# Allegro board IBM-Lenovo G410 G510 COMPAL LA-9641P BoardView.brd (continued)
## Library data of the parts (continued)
Q107 Q108 Q110 Q111 Q113 Q116 Q118 Q120 QV1 QV2 QV6 QV7 QV9 = 2N7002_SOT23-3
Q121 QV8 = AP2301GN-HF_SOT23-3
R297 R299 R300 R302 R550-R553 R813 RT1 = R0805_0OHM
RL14 = R_0805
RP1 RP2 RP5 RP6 RP9 RP10 RP12 RP16-RP19 RP21-RP23 = RP_0804_8P4R
RP13-RP15 = RP_1206_10P8R
SW4-SW7 = SW_TJG-533-V-T-R_6P
T1-T4 T6 T12-T28 T31 T66 TV12-TV15 = TPC12
TL1 = BOTH_NS0013LF_16P
U1 = 74AHC1G09GW_TSSOP5
U4 = DH82LPMS-QC4C_FCBGA_695P_A39
U6 UV2 = NC7SZ08P5X_NL_SC70-5
U8 = MX25L1605AM2C-12G_SO8
U9 = ADM1032ARMZ-2REEL_MSOP8
U10 = TPD7S019-15DBQR_SSOP16
U31 = KB9012QF-A2_LQFP128_14X14
U35 U36 = G547I2P81U_MSOP8
U38 U39 = DMN3030LSS-13_SOP8L-8
U72 = APL3512ABI-TRG_SOT23-5
U73 = AP2330W-7_SC59-3
UA1 = CX20751-11Z_QFN40_5X5
UL1 = AR8161-AL3A-R_QFN40_5X5
UT2 = RTD2132S-GR_QFN32_5X5
UV1 = MARS-PRO_FCBGA_962P_A39
UV4 = AO4304L_SO8
UV5-UV8 = MT41J128M16JT-093_FBGA_96P_A39
UV9-UV12 = K4W4G1646B-HC11_FBGA_96P_A39
Y1 = Y_CM31532768DZFT_2P
Y2 YL1 YV1 = Y_X3G025000DC1H_4P

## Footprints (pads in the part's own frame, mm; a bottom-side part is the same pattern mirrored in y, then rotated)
1N4148WS-7-F_SOD323-2
  rect 1.346x0.66 smd: 1(0,0) 2(2.4,0)
1SS355_SOD323-2
  rect 0.787x0.889 smd: 1(0,0) 2(2.2,0)
2N7002_SOT23-3
  oval 1.016x1.524 smd: 1(0,0) 2(0.965,2.083) 3(-0.965,2.083)
2N7002DW-7-F_SOT363-6
  oval 0.432x0.61 smd: 1(0,0) 2(0.65,0) 3(1.3,0) 4(1.3,1.9) 5(0.65,1.9) 6(0,1.9)
2N7002DW-T-R7_SOT363-6
  oval 0.381x1.397 smd: 1(0,0) 2(0.65,0) 3(1.3,0) 4(1.3,1.725) 5(0.65,1.725) 6(0,1.725)
2N7002H_SOT23-3
  oval 1.016x1.524 smd: 1(0,0) 2(0.965,2.083) 3(-0.965,2.083)
2N7002KW_SOT323-3
  oval 0.813x0.914 smd: 1(0,0) 2(0.65,1.6) 3(-0.65,1.6)
2N7002W-T-R7_SOT323-3
  oval 0.813x0.914 smd: 1(0,0) 2(0.65,1.6) 3(-0.65,1.6)
74AHC1G09GW_TSSOP5
  oval 0.381x1.346 smd: 1(0,0) 2(0.65,0) 3(1.3,0) 4(1.3,1.79) 5(0,1.79)
ACES_50208-00601-P01_6P
  oval 0.508x0.991 smd: 1(0,0) 2(-0.8,0) 3(-1.6,0) 4(-2.4,0) 5(-3.2,0) 6(-4,0)
  rect 1.194x1.702 smd: 7(-5.3,-1.95) 8(1.3,-1.95)
ACES_50271-0020N-001_2P
  oval 0.787x1.6 smd: 1(0,0) 2(1.25,0)
  rect 2.108x2.997 smd: 3(3.8,-2.9) 4(-2.55,-2.9)
ACES_50312-00541-001_5P-T
  round 1.397 hole 0.991: 1(0,0) 2(2,0) 3(4,0) 4(6,0) 5(8,0)
ACES_85205-0400_4P
  oval 0.813x1.626 smd: 1(0,0) 2(1.25,0) 3(2.5,0) 4(3.75,0)
  rect 2.032x3.048 smd: 5(-2.55,-2.9) 6(6.3,-2.9)
ACES_85205-04001_4P
  oval 0.787x1.6 smd: 1(0,0) 2(1.25,0) 3(2.5,0) 4(3.75,0)
  rect 2.108x2.997 smd: 5(-2.55,-2.9) 6(6.3,-2.9)
ACES_88058-060N_6P
  oval 0.61x1.092 smd: 1(0,0) 2(-1,0) 3(-2,0) 4(-3,0) 5(-4,0) 6(-5,0)
  rect 2.388x2.997 smd: 7(2.9,-2.05) 8(-7.9,-2.05)
ACES_88341-3001_30P
  round 1.092 hole 1.092 unplated: (-2.3,-1.95) (16.8,-1.95)
  oval 0.254x1.295 smd: 1(0,0) 2(0.5,0) 3(1,0) 4(1.5,0) 5(2,0) 6(2.5,0) 7(3,0) 8(3.5,0) 9(4,0) 10(4.5,0) 11(5,0) 12(5.5,0) 13(6,0) 14(6.5,0) 15(7,0) 16(7.5,0) 17(8,0) 18(8.5,0) 19(9,0) 20(9.5,0) 21(10,0) 22(10.5,0) 23(11,0) 24(11.5,0) 25(12,0) 26(12.5,0) 27(13,0) 28(13.5,0) 29(14,0) 30(14.5,0)
  rect 1.549x3.404 smd: 31(-4.125,-5.85) 32(18.625,-5.85)
  rect 2.007x2.997 smd: 33(3.5,-6.05) 34(11,-6.05)
ACES_88514-2401_24P-T
  oval 0.61x1.295 smd: 1(0,0) 2(-1,0) 3(-2,0) 4(-3,0) 5(-4,0) 6(-5,0) 7(-6,0) 8(-7,0) 9(-8,0) 10(-9,0) 11(-10,0) 12(-11,0) 13(-12,0) 14(-13,0) 15(-14,0) 16(-15,0) 17(-16,0) 18(-17,0) 19(-18,0) 20(-19,0) 21(-20,0) 22(-21,0) 23(-22,0) 24(-23,0)
  rect 2.159x2.21 smd: 25(-25.825,-3.05) 26(2.825,-3.05)
ACES_88514-3001_30P
  oval 0.61x1.295 smd: 1(0,0) 2(1,0) 3(2,0) 4(3,0) 5(4,0) 6(5,0) 7(6,0) 8(7,0) 9(8,0) 10(9,0) 11(10,0) 12(11,0) 13(12,0) 14(13,0) 15(14,0) 16(15,0) 17(16,0) 18(17,0) 19(18,0) 20(19,0) 21(20,0) 22(21,0) 23(22,0) 24(23,0) 25(24,0) 26(25,0) 27(26,0) 28(27,0) 29(28,0) 30(29,0)
  rect 2.159x2.21 smd: 31(-2.825,-3.05) 32(31.825,-3.05)
ADM1032ARMZ-2REEL_MSOP8
  oval 0.381x1.626 smd: 1(0,0) 2(0.65,0) 3(1.3,0) 4(1.95,0) 5(1.95,4.3) 6(1.3,4.3) 7(0.65,4.3) 8(0,4.3)
ALLTO_C18518-11305-L_13P-T
  round 1.194 hole 1.194 unplated: (-19.18,-1.56) (0.42,-1.56)
  round 1.067 hole 0.711: 1(0,0) 2(-1.27,0) 3(-2.54,0) 4(-3.81,0) 5(-5.08,0) 6(-6.35,0) 7(-7.62,0)
  round 1.016 hole 0.61: 8(-13.83,1) 9(-14.83,0) 10(-15.83,1) 11(-16.83,0) 12(-17.83,1) 13(-18.83,0)
  oval 1.803x3.302 hole 0.991x2.489: 14(-20.98,-0.29) 15(2.22,-0.29)
AO4304L_SO8
  oval 0.635x1.854 smd: 1(0,0) 2(1.27,0) 3(2.54,0) 4(3.81,0) 5(3.81,5.165) 6(2.54,5.165) 7(1.27,5.165) 8(0,5.165)
AO4407A_SO8
  oval 0.635x1.854 smd: 1(0,0) 2(1.27,0) 3(2.54,0) 4(3.81,0) 5(3.81,5.165) 6(2.54,5.165) 7(1.27,5.165) 8(0,5.165)
AO4466L_SO8
  oval 0.635x1.854 smd: 1(0,0) 2(1.27,0) 3(2.54,0) 4(3.81,0) 5(3.81,5.165) 6(2.54,5.165) 7(1.27,5.165) 8(0,5.165)
AP2301GN-HF_SOT23-3
  oval 1.016x1.524 smd: 1(0,0) 2(0.965,2.083) 3(-0.965,2.083)
AP2330W-7_SC59-3
  oval 0.787x0.991 smd: 1(0,0) 2(-0.95,-2.4) 3(0.95,-2.4)
APL3512ABI-TRG_SOT23-5
  oval 0.61x1.041 smd: 1(0,0) 2(0.95,0) 3(1.9,0) 4(1.9,2.7) 5(0,2.7)
AR8161-AL3A-R_QFN40_5X5
  oval 0.203x1.016 smd: 1(0,0) 2(0.4,0) 3(0.8,0) 4(1.2,0) 5(1.6,0) 6(2,0) 7(2.4,0) 8(2.8,0) 9(3.2,0) 10(3.6,0) 21(3.6,4.975) 22(3.2,4.975) 23(2.8,4.975) 24(2.4,4.975) 25(2,4.975) 26(1.6,4.975) 27(1.2,4.975) 28(0.8,4.975) 29(0.4,4.975) 30(0,4.975)
  oval 1.016x0.203 smd: 11(4.288,0.688) 12(4.288,1.088) 13(4.288,1.488) 14(4.288,1.888) 15(4.288,2.288) 16(4.288,2.688) 17(4.288,3.088) 18(4.288,3.488) 19(4.288,3.888) 20(4.288,4.288) 31(-0.688,4.288) 32(-0.688,3.888) 33(-0.688,3.488) 34(-0.688,3.088) 35(-0.688,2.688) 36(-0.688,2.288) 37(-0.688,1.888) 38(-0.688,1.488) 39(-0.688,1.088) 40(-0.688,0.688)
  rect 3.302x3.302 smd: 41(1.8,2.488)
AZ5125-02SPR7G_SOT23-3
  oval 1.016x1.524 smd: 1(0,0) 2(0.965,2.083) 3(-0.965,2.083)
AZC099-04SPR7G_SOT23-6
  oval 0.559x1.092 smd: 1(0,0) 2(0.95,0) 3(1.9,0) 4(1.9,2.5) 5(0.95,2.5) 6(0,2.5)
BELLW_80003-8041_52P
  round 1.6 hole 1.6 unplated: (-0.7,4.1)
  round 1.092 hole 1.092 unplated: (24.3,4.1)
  oval 0.61x2.007 smd: 1(0,0) 2(0.4,8.2) 3(0.8,0) 4(1.2,8.2) 5(1.6,0) 6(2,8.2) 7(2.4,0) 8(2.8,8.2) 9(3.2,0) 10(3.6,8.2) 11(4,0) 12(4.4,8.2) 13(4.8,0) 14(5.2,8.2) 15(5.6,0) 16(6,8.2) 17(9.6,0) 18(10,8.2) 19(10.4,0) 20(10.8,8.2) 21(11.2,0) 22(11.6,8.2) 23(12,0) 24(12.4,8.2) 25(12.8,0) 26(13.2,8.2) 27(13.6,0) 28(14,8.2) 29(14.4,0) 30(14.8,8.2) 31(15.2,0) 32(15.6,8.2) 33(16,0) 34(16.4,8.2) 35(16.8,0) 36(17.2,8.2) 37(17.6,0) 38(18,8.2) 39(18.4,0) 40(18.8,8.2) 41(19.2,0) 42(19.6,8.2) 43(20,0) 44(20.4,8.2) 45(20.8,0) 46(21.2,8.2) 47(21.6,0) 48(22,8.2) 49(22.4,0) 50(22.8,8.2) 51(23.2,0) 52(23.6,8.2)
  rect 2.311x3.2 smd: 53(-2.85,0.6) 54(26.45,0.6)
BOTH_NS0013LF_16P
  oval 0.762x1.905 smd: 1(0,0) 2(1.27,0) 3(2.54,0) 4(3.81,0) 5(5.08,0) 6(6.35,0) 7(7.62,0) 8(8.89,0) 9(8.89,8.8) 10(7.62,8.8) 11(6.35,8.8) 12(5.08,8.8) 13(3.81,8.8) 14(2.54,8.8) 15(1.27,8.8) 16(0,8.8)
BQ24737RGRR_VQFN20_3P5X3P5
  oval 0.254x1.041 smd: 1(0,0) 2(0.5,0) 3(1,0) 4(1.5,0) 5(2,0) 11(2,3.45) 12(1.5,3.45) 13(1,3.45) 14(0.5,3.45) 15(0,3.45)
  oval 1.041x0.254 smd: 6(2.725,0.725) 7(2.725,1.225) 8(2.725,1.725) 9(2.725,2.225) 10(2.725,2.725) 16(-0.725,2.725) 17(-0.725,2.225) 18(-0.725,1.725) 19(-0.725,1.225) 20(-0.725,0.725)
  rect 2.057x2.057 smd: 21(1,1.725)
BS4200N-C-LV_SMB-F2
  rect 2.159x2.743 smd: 1(0,0) 2(4.42,0)
C_6SVPE220MX
  oval 3.505x1.6 smd: 1(0,0) 2(5.6,0)
C_0402
  rect 0.508x0.559 smd: 1(0,0) 2(0.914,0)
C_0603
  rect 0.635x0.889 smd: 1(0,0) 2(1.397,0)
C_0805
  rect 0.813x1.397 smd: 1(0,0) 2(1.702,0)
C_B2
  rect 1.346x2.692 smd: 1(0,0) 2(-2.75,0)
C_D2
  rect 2.388x2.794 smd: 1(0,0) 2(6.4,0)
C_EEEFZ1E101P
  oval 3.2x1.6 smd: 1(0,0) 2(5,0)
C_FP-2R5ME331M-SLR
  oval 3.505x1.6 smd: 1(0,0) 2(-5.6,0)
C_MP2VLPS330MC4R2
  oval 3.505x1.6 smd: 1(0,0) 2(-5.6,0)
C_MP6VL220MC6
  oval 3.505x1.6 smd: 1(0,0) 2(5.6,0)
C_MP6VLPS220MC4R2
  oval 3.505x1.6 smd: 1(0,0) 2(-5.6,0)
C_MVY25VC220MH10E0-J
  oval 4.191x2.21 smd: 1(0,0) 2(-7.3,0)
CH751H-40PT_SOD323-2
  rect 0.711x0.711 smd: 1(0,0) 2(2.33,0)
CHENG_MBK1608121YZF_2P
  rect 0.991x0.787 smd: 1(0,0) 2(1.6,0)
CHENG_SMB3025500YA_2P
  rect 2.997x1.803 smd: 1(0,0) 2(4,0)
CONTE_80431-5K1-152_15P
  oval 0.965x1.321 hole 0.711: 1(0,0) 2(2.29,0) 3(4.58,0) 4(6.87,0) 5(9.16,0) 6(-1.145,0) 7(1.145,0) 8(3.435,0) 9(5.725,0) 10(8.015,0)
  round 1.016 hole 0.711: 11(0,1.4) 12(2.29,1.4) 13(4.58,1.4) 14(6.87,1.4) 15(9.16,1.4)
  oval 1.372x3.251 hole 0.61x2.489: 16(-5.47,-0.1) 17(14.63,-0.1)
CSD87351Q5D_SON8-7
  oval 1.93x0.838 smd: 1(0,0)
  oval 0.66x0.838 smd: 2(1.905,0) 3(3.175,0) 4(3.175,5.39) 5(1.905,5.39) 6(0.635,5.39) 7(-0.635,5.39)
  custom 0.87x0.87 smd: 8(1.27,2.695)
CVILU_CF06041H0RB-NH_4P
  oval 0.305x1.143 smd: 1(0,0) 2(1,0) 3(2,0) 4(3,0)
  rect 1.397x2.311 smd: 5(-1.75,-3.825) 6(4.75,-3.825)
CX20751-11Z_QFN40_5X5
  oval 0.203x1.016 smd: 1(0,0) 2(0.4,0) 3(0.8,0) 4(1.2,0) 5(1.6,0) 6(2,0) 7(2.4,0) 8(2.8,0) 9(3.2,0) 10(3.6,0) 21(3.6,4.975) 22(3.2,4.975) 23(2.8,4.975) 24(2.4,4.975) 25(2,4.975) 26(1.6,4.975) 27(1.2,4.975) 28(0.8,4.975) 29(0.4,4.975) 30(0,4.975)
  oval 1.016x0.203 smd: 11(4.288,0.688) 12(4.288,1.088) 13(4.288,1.488) 14(4.288,1.888) 15(4.288,2.288) 16(4.288,2.688) 17(4.288,3.088) 18(4.288,3.488) 19(4.288,3.888) 20(4.288,4.288) 31(-0.688,4.288) 32(-0.688,3.888) 33(-0.688,3.488) 34(-0.688,3.088) 35(-0.688,2.688) 36(-0.688,2.288) 37(-0.688,1.888) 38(-0.688,1.488) 39(-0.688,1.088) 40(-0.688,0.688)
  rect 3.302x3.302 smd: 41(1.8,2.488)
CYNTE_PCMB063T-1R0MS_2P
  rect 2.159x3.505 smd: 1(0,0) 2(5.85,0)
CYNTE_PCMB063T-100MS_2P
  rect 2.362x3.505 smd: 1(0,0) 2(6.05,0)
CYNTE_PCMB104T-1R0MH_2P
  rect 3.81x3.988 smd: 1(0,0) 2(9.2,0)
CYNTE_PDME064T-R36MS1R405_4P
  custom 0.686x0.686 smd: 1(0,0) 4(8.509,0)
  rect 2.362x0.508 smd: 2(1.448,0) 3(7.061,0)
CYNTE_PG031B-4R7MS_2P
  rect 0.889x1.194 smd: 1(0,0) 2(2.2,0)
CYNTE_PHT32251B-1R0MS_2P
  rect 0.991x2.591 smd: 1(0,0) 2(2.3,0)
DAN202UT106_SC70-3
  oval 0.787x0.889 smd: 1(0,0) 2(0.65,1.6) 3(-0.65,1.6)
DELTA_SIA4012-4R7M_2P
  rect 1.194x4.191 smd: 1(0,0) 2(3,0)
DH82LPMS-QC4C_FCBGA_695P_A39
  round 0.483 smd: A2(0.624,0) A44(18.101,0) B1(0,-0.624) B45(18.625,-0.524) BD1(0,-18.101) BD45(18.625,-18.101) BE2(0.524,-18.625) BE44(18.101,-18.625)
  round 0.356 smd: A4(1.217,0) A5(1.81,0) A41(16.915,0) A43(17.508,0) B2(0.603,-0.603) B44(18.022,-0.603) BA1(0,-16.915) BA45(18.625,-16.915) BC1(0,-17.508) BC45(18.625,-17.508) BD2(0.603,-18.022) BD44(18.022,-18.022) BE3(1.117,-18.625) BE5(1.71,-18.625) BE41(16.915,-18.625) BE43(17.508,-18.625) C45(18.625,-1.117) D1(0,-1.217) E1(0,-1.81) E45(18.625,-1.71)
  round 0.33 smd: A6(2.483,0) A40(16.242,0) AY1(0,-16.242) AY45(18.625,-16.242) BE6(2.383,-18.625) BE40(16.242,-18.625) F1(0,-2.483) F45(18.625,-2.383)
  round 0.305 smd: A8(3.216,0) A10(4.029,0) A12(4.842,0) A14(5.655,0) A16(6.468,0) A18(7.28,0) A20(8.093,0) A22(8.906,0) A24(9.719,0) A26(10.532,0) A28(11.344,0) A30(12.157,0) A32(12.97,0) A34(13.783,0) A36(14.596,0) A38(15.408,0) AA2(0.452,-8.478) AA4(1.336,-8.5) AA14(5.515,-8.827) AA16(6.328,-8.827) AA18(7.141,-8.827) AA20(7.954,-8.827) AA22(8.766,-8.827) AA24(9.579,-8.827) AA26(10.392,-8.827) AA28(11.205,-8.827) AA30(12.018,-8.827) AA32(12.83,-8.827) AA42(17.289,-8.5) AA44(18.173,-8.521) AB1(0,-8.906) AB3(0.904,-8.906) AB6(1.934,-9.008) AB7(2.531,-9.008) AB8(3.128,-9.008) AB10(3.724,-9.008) AB11(4.321,-9.008) AB12(4.918,-9.008) AB34(13.707,-9.008) AB35(14.304,-9.008) AB36(14.9,-9.008) AB38(15.497,-9.008) AB39(16.094,-9.008) AB40(16.691,-9.008) AB43(17.721,-8.906) AB45(18.625,-8.906) AC2(0.472,-9.312) AC44(18.152,-9.312) AD1(0,-9.719) AD3(0.904,-9.719) AD6(1.934,-9.617) AD7(2.531,-9.617) AD8(3.128,-9.617) AD10(3.724,-9.617) AD11(4.321,-9.617) AD12(4.918,-9.617) AD14(5.515,-9.488) AD16(6.328,-9.488) AD18(7.141,-9.488) AD20(7.954,-9.488) AD22(8.766,-9.488) AD24(9.579,-9.488) AD26(10.392,-9.488) AD28(11.205,-9.488) AD30(12.018,-9.488) AD32(12.83,-9.488) AD34(13.707,-9.617) AD35(14.304,-9.617) AD36(14.9,-9.617) AD38(15.497,-9.617) AD39(16.094,-9.617) AD40(16.691,-9.617) AD43(17.721,-9.719) AD45(18.625,-9.719) AE2(0.452,-10.103) AE4(1.336,-10.125) AE14(5.515,-10.148) AE16(6.328,-10.148) AE18(7.141,-10.148) AE20(7.954,-10.148) AE22(8.766,-10.148) AE24(9.579,-10.148) AE26(10.392,-10.148) AE28(11.205,-10.148) AE30(12.018,-10.148) AE32(12.83,-10.148) AE42(17.289,-10.125) AE44(18.173,-10.147) AF1(0,-10.532) AF3(0.904,-10.532) AF6(1.934,-10.595) AF7(2.531,-10.595) AF8(3.128,-10.595) AF10(3.724,-10.595) AF11(4.321,-10.595) AF12(4.918,-10.595) AF34(13.707,-10.595) AF35(14.304,-10.595) AF36(14.9,-10.595) AF38(15.497,-10.595) AF39(16.094,-10.595) AF40(16.691,-10.595) AF43(17.721,-10.532) AF45(18.625,-10.532) AG2(0.472,-10.938) AG14(5.515,-10.808) AG16(6.328,-10.808) AG18(7.141,-10.808) AG20(7.954,-10.808) AG22(8.766,-10.808) AG24(9.579,-10.808) AG26(10.392,-10.808) AG28(11.205,-10.808) AG30(12.018,-10.808) AG32(12.83,-10.808) AG44(18.152,-10.938) AH1(0,-11.344) AH3(0.904,-11.344) AH43(17.721,-11.344) AH45(18.625,-11.344) AJ2(0.452,-11.729) AJ4(1.336,-11.751) AJ6(1.934,-11.573) AJ7(2.531,-11.573) AJ8(3.128,-11.573) AJ10(3.724,-11.573) AJ11(4.321,-11.573) AJ12(4.918,-11.573) AJ14(5.515,-11.469) AJ16(6.328,-11.469) AJ18(7.141,-11.469) AJ20(7.954,-11.469) AJ22(8.766,-11.469) AJ24(9.579,-11.469) AJ26(10.392,-11.469) AJ28(11.205,-11.469) AJ30(12.018,-11.469) AJ32(12.83,-11.469) AJ34(13.707,-11.573) AJ35(14.304,-11.573) AJ36(14.9,-11.573) AJ38(15.497,-11.573) AJ39(16.094,-11.573) AJ40(16.691,-11.573) AJ42(17.289,-11.751) AJ44(18.173,-11.773) AK1(0,-12.157) AK3(0.904,-12.157) AK14(5.515,-12.129) AK16(6.328,-12.129) AK18(7.141,-12.129) AK20(7.954,-12.129) AK22(8.766,-12.129) AK24(9.579,-12.129) AK26(10.392,-12.129) AK28(11.205,-12.129) AK30(12.018,-12.129) AK32(12.83,-12.129) AK43(17.721,-12.157) AK45(18.625,-12.157) AL2(0.472,-12.564) AL6(1.934,-12.551) AL7(2.531,-12.551) AL8(3.128,-12.551) AL10(3.724,-12.551) AL11(4.321,-12.551) AL12(4.918,-12.551) AL34(13.707,-12.551) AL35(14.304,-12.551) AL36(14.9,-12.551) AL38(15.497,-12.551) AL39(16.094,-12.551) AL40(16.691,-12.551) AL44(18.152,-12.564) AM1(0,-12.97) AM3(0.904,-12.97) AM14(5.515,-12.79) AM16(6.328,-12.79) AM18(7.141,-12.79) AM20(7.954,-12.79) AM22(8.766,-12.79) AM24(9.579,-12.79) AM26(10.392,-12.79) AM28(11.205,-12.79) AM30(12.018,-12.79) AM32(12.83,-12.79) AM43(17.721,-12.97) AM45(18.625,-12.97) AN2(0.452,-13.355) AN4(1.336,-13.376) AN6(1.934,-13.529) AN7(2.531,-13.529) AN8(3.128,-13.529) AN10(3.724,-13.529) AN11(4.321,-13.529) AN34(13.656,-13.529) AN35(14.304,-13.529) AN36(14.9,-13.529) AN38(15.497,-13.529) AN39(16.094,-13.529) AN40(16.691,-13.529) AN42(17.289,-13.376) AN44(18.173,-13.398) AP1(0,-13.783) AP3(0.904,-13.783) AP13(5.096,-13.656) AP15(6.074,-13.707) AP17(7.052,-13.707) AP20(8.03,-13.707) AP22(9.008,-13.707) AP24(9.617,-13.707) AP26(10.595,-13.707) AP29(11.573,-13.707) AP31(12.551,-13.707) AP43(17.721,-13.783) AP45(18.625,-13.783) AR2(0.472,-14.189) AR13(5.096,-14.304) AR15(6.074,-14.304) AR17(7.052,-14.304) AR20(8.03,-14.304) AR22(9.008,-14.304) AR24(9.617,-14.304) AR26(10.595,-14.304) AR29(11.573,-14.304) AR31(12.551,-14.304) AR33(13.529,-14.304) AR44(18.152,-14.189) AT1(0,-14.596) AT3(0.904,-14.596) AT6(1.934,-14.507) AT7(2.531,-14.507) AT8(3.128,-14.507) AT10(4.118,-14.9) AT13(5.096,-14.9) AT15(6.074,-14.9) AT17(7.052,-14.9) AT20(8.03,-14.9) AT22(9.008,-14.9) AT24(9.617,-14.9) AT26(10.595,-14.9) AT29(11.573,-14.9) AT31(12.551,-14.9) AT33(13.529,-14.9) AT36(14.9,-14.507) AT38(15.497,-14.507) AT39(16.094,-14.507) AT40(16.691,-14.507) AT43(17.721,-14.596) AT45(18.625,-14.596) AU2(0.452,-14.98) AU4(1.336,-15.002) AU42(17.289,-15.002) AU44(18.173,-15.024) AV1(0,-15.408) AV3(0.904,-15.408) AV6(1.934,-15.485) AV7(2.531,-15.485) AV10(4.118,-15.497) AV13(5.096,-15.497) AV15(6.074,-15.497) AV17(7.052,-15.497) AV20(8.03,-15.497) AV22(9.008,-15.497) AV24(9.617,-15.497) AV26(10.595,-15.497) AV29(11.573,-15.497) AV31(12.551,-15.497) AV33(13.529,-15.497) AV36(14.507,-15.497) AV40(16.691,-15.485) AV43(17.721,-15.408) AV45(18.625,-15.408) AW2(0.472,-15.815) AW8(3.14,-16.094) AW10(4.118,-16.094) AW13(5.096,-16.094) AW15(6.074,-16.094) AW17(7.052,-16.094) AW20(8.03,-16.094) AW22(9.008,-16.094) AW24(9.617,-16.094) AW26(10.595,-16.094) AW29(11.573,-16.094) AW31(12.551,-16.094) AW33(13.529,-16.094) AW36(14.507,-16.094) AW38(15.485,-16.094) AW40(17.123,-16.221) AW44(18.152,-15.815) AY3(0.978,-16.221) AY5(1.743,-16.051) AY7(2.404,-17.123) AY8(3.14,-16.691) AY10(4.118,-16.691) AY13(5.096,-16.691) AY15(6.074,-16.691) AY17(7.052,-16.691) AY20(8.03,-16.691) AY22(9.008,-16.691) AY24(9.617,-16.691) AY26(10.595,-16.691) AY29(11.573,-16.691) AY31(12.551,-16.691) AY33(13.529,-16.691) AY36(14.507,-16.691) AY38(15.485,-16.691) AY43(17.721,-16.221) B7(2.739,-0.552) B9(3.645,-0.452) B11(4.436,-0.472) B13(5.27,-0.452) B15(6.061,-0.472) B17(6.896,-0.452) B19(7.687,-0.472) B21(8.521,-0.452) B23(9.312,-0.472) B25(10.147,-0.452) B27(10.938,-0.472) B29(11.773,-0.452) B31(12.564,-0.472) B33(13.398,-0.452) B35(14.189,-0.472) B37(15.024,-0.452) B39(15.815,-0.472) BA40(16.051,-16.882) BB9(3.623,-17.289) BB13(5.248,-17.289) BB17(6.874,-17.289) BB21(8.5,-17.289) BB25(10.125,-17.289) BB29(11.751,-17.289) BB33(13.376,-17.289) BB37(15.002,-17.289) BC6(2.404,-17.721) BC8(3.216,-17.721) BC10(4.029,-17.721) BC12(4.842,-17.721) BC14(5.655,-17.721) BC16(6.468,-17.721) BC18(7.28,-17.721) BC20(8.093,-17.721) BC22(8.906,-17.721) BC24(9.719,-17.721) BC26(10.532,-17.721) BC28(11.344,-17.721) BC30(12.157,-17.721) BC32(12.97,-17.721) BC34(13.783,-17.721) BC36(14.596,-17.721) BC38(15.408,-17.721) BC40(16.221,-17.647) BD7(2.81,-18.152) BD9(3.601,-18.173) BD11(4.436,-18.152) BD13(5.227,-18.173) BD15(6.061,-18.152) BD17(6.852,-18.173) BD19(7.687,-18.152) BD21(8.478,-18.173) BD23(9.312,-18.152) BD25(10.103,-18.173) BD27(10.938,-18.152) BD29(11.729,-18.173) BD31(12.564,-18.152) BD33(13.355,-18.173) BD35(14.189,-18.152) BD37(14.98,-18.173) BD39(15.815,-18.152) BE8(3.216,-18.625) BE10(4.029,-18.625) BE12(4.842,-18.625) BE14(5.655,-18.625) BE16(6.468,-18.625) BE18(7.28,-18.625) BE20(8.093,-18.625) BE22(8.906,-18.625) BE24(9.719,-18.625) BE26(10.532,-18.625) BE28(11.344,-18.625) BE30(12.157,-18.625) BE32(12.97,-18.625) BE34(13.783,-18.625) BE36(14.596,-18.625) BE38(15.408,-18.625) C6(2.37,-1.017) C8(3.216,-0.904) C10(4.029,-0.904) C12(4.842,-0.904) C14(5.655,-0.904) C16(6.468,-0.904) C18(7.28,-0.904) C20(8.093,-0.904) C22(8.906,-0.904) C24(9.719,-0.904) C26(10.532,-0.904) C28(11.344,-0.904) C30(12.157,-0.904) C32(12.97,-0.904) C34(13.783,-0.904) C36(14.596,-0.904) C38(15.408,-0.904) C40(16.221,-0.904) D9(3.623,-1.336) D13(5.248,-1.336) D17(6.874,-1.336) D21(8.5,-1.336) D25(10.125,-1.336) D29(11.751,-1.336) D33(13.376,-1.336) D37(15.002,-1.336) E6(2.574,-1.743) F3(0.978,-2.359) F8(3.14,-1.934) F10(4.118,-1.934) F13(5.096,-1.934) F15(6.074,-1.934) F17(7.052,-1.934) F20(8.03,-1.934) F22(9.008,-1.934) F24(9.617,-1.934) F26(10.595,-1.934) F29(11.573,-1.934) F31(12.551,-1.934) F33(13.529,-1.934) F36(14.507,-1.934) F38(15.485,-1.934) F39(16.221,-1.502) F41(16.882,-2.574) F43(17.647,-2.404) G2(0.532,-2.752) G5(1.562,-2.48) G8(3.14,-2.531) G10(4.118,-2.531) G13(5.096,-2.531) G15(6.074,-2.531) G17(7.052,-2.531) G20(8.03,-2.531) G22(9.008,-2.531) G24(9.617,-2.531) G26(10.595,-2.531) G29(11.573,-2.531) G31(12.551,-2.531) G33(13.529,-2.531) G36(14.507,-2.531) G38(15.485,-2.531) G44(18.152,-2.81) H1(0,-3.216) H3(0.904,-3.216) H6(1.934,-3.14) H7(2.531,-3.14) H10(4.118,-3.128) H13(5.096,-3.128) H15(6.074,-3.128) H17(7.052,-3.128) H20(8.03,-3.128) H22(9.008,-3.128) H24(9.617,-3.128) H26(10.595,-3.128) H29(11.573,-3.128) H31(12.551,-3.128) H33(13.529,-3.128) H36(14.507,-3.128) H39(16.094,-3.14) H40(16.691,-3.14) H43(17.721,-3.216) H45(18.625,-3.216) J2(0.452,-3.601) J4(1.336,-3.623) J42(17.289,-3.623) J44(18.173,-3.645) K1(0,-4.029) K3(0.904,-4.029) K6(1.934,-4.118) K7(2.531,-4.118) K8(3.128,-4.118) K10(3.724,-4.118) K13(5.096,-3.724) K15(6.074,-3.724) K17(7.052,-3.724) K20(8.03,-3.724) K22(9.008,-3.724) K24(9.617,-3.724) K26(10.595,-3.724) K29(11.573,-3.724) K31(12.551,-3.724) K33(13.529,-3.724) K36(14.507,-3.724) K38(15.497,-4.118) K39(16.094,-4.118) K40(16.691,-4.118) K43(17.721,-4.029) K45(18.625,-4.029) L2(0.472,-4.436) L13(5.096,-4.321) L15(6.074,-4.321) L17(7.052,-4.321) L20(8.03,-4.321) L22(9.008,-4.321) L24(9.617,-4.321) L26(10.595,-4.321) L29(11.573,-4.321) L31(12.551,-4.321) L33(13.529,-4.321) L44(18.152,-4.436) M1(0,-4.842) M3(0.904,-4.842) M15(6.074,-4.918) M17(7.052,-4.918) M20(8.03,-4.918) M22(9.008,-4.918) M24(9.617,-4.918) M26(10.595,-4.918) M29(11.573,-4.918) M31(12.551,-4.918) M33(13.529,-4.969) M43(17.721,-4.842) M45(18.625,-4.842) N2(0.452,-5.227) N4(1.336,-5.248) N6(1.934,-5.096) N7(2.531,-5.096) N8(3.128,-5.096) N10(3.724,-5.096) N11(4.321,-5.096) N12(4.969,-5.096) N35(14.304,-5.096) N36(14.9,-5.096) N38(15.497,-5.096) N39(16.094,-5.096) N40(16.691,-5.096) N42(17.289,-5.248) N44(18.173,-5.27) P1(0,-5.655) P3(0.904,-5.655) P14(5.515,-5.525) P16(6.328,-5.525) P18(7.141,-5.525) P20(7.954,-5.525) P22(8.766,-5.525) P24(9.579,-5.525) P26(10.392,-5.525) P28(11.205,-5.525) P30(12.018,-5.525) P32(12.83,-5.525) P43(17.721,-5.655) P45(18.625,-5.655) R2(0.472,-6.061) R6(1.934,-6.074) R7(2.531,-6.074) R8(3.128,-6.074) R10(3.724,-6.074) R11(4.321,-6.074) R12(4.918,-6.074) R14(5.515,-6.186) R16(6.328,-6.186) R18(7.141,-6.186) R20(7.954,-6.186) R22(8.766,-6.186) R24(9.579,-6.186) R26(10.392,-6.186) R28(11.205,-6.186) R30(12.018,-6.186) R32(12.83,-6.186) R34(13.707,-6.074) R35(14.304,-6.074) R36(14.9,-6.074) R38(15.497,-6.074) R39(16.094,-6.074) R40(16.691,-6.074) R44(18.152,-6.061) T1(0,-6.468) T3(0.904,-6.468) T43(17.721,-6.468) T45(18.625,-6.468) U2(0.452,-6.852) U4(1.336,-6.874) U6(1.934,-7.052) U7(2.531,-7.052) U8(3.128,-7.052) U10(3.724,-7.052) U11(4.321,-7.052) U12(4.918,-7.052) U14(5.515,-6.846) U16(6.328,-6.846) U18(7.141,-6.846) U20(7.954,-6.846) U22(8.766,-6.846) U24(9.579,-6.846) U26(10.392,-6.846) U28(11.205,-6.846) U30(12.018,-6.846) U32(12.83,-6.846) U34(13.707,-7.052) U35(14.304,-7.052) U36(14.9,-7.052) U38(15.497,-7.052) U39(16.094,-7.052) U40(16.691,-7.052) U42(17.289,-6.874) U44(18.173,-6.896) V1(0,-7.28) V3(0.904,-7.28) V14(5.515,-7.506) V16(6.328,-7.506) V18(7.141,-7.506) V20(7.954,-7.506) V22(8.766,-7.506) V24(9.579,-7.506) V26(10.392,-7.506) V28(11.205,-7.506) V30(12.018,-7.506) V32(12.83,-7.506) V43(17.721,-7.28) V45(18.625,-7.28) W2(0.472,-7.687) W44(18.152,-7.687) Y1(0,-8.093) Y3(0.904,-8.093) Y6(1.934,-8.03) Y7(2.531,-8.03) Y8(3.128,-8.03) Y10(3.724,-8.03) Y11(4.321,-8.03) Y12(4.918,-8.03) Y14(5.515,-8.167) Y16(6.328,-8.167) Y18(7.141,-8.167) Y20(7.954,-8.167) Y22(8.766,-8.167) Y24(9.579,-8.167) Y26(10.392,-8.167) Y28(11.205,-8.167) Y30(12.018,-8.167) Y32(12.83,-8.167) Y34(13.707,-8.03) Y35(14.304,-8.03) Y36(14.9,-8.03) Y38(15.497,-8.03) Y39(16.094,-8.03) Y40(16.691,-8.03) Y43(17.721,-8.093) Y45(18.625,-8.093)
  round 0.432 smd: B4(1.315,-0.586) B42(17.233,-0.637) BA2(0.551,-16.664) BB2(0.563,-17.31) BB44(17.988,-17.233) BD4(1.391,-17.988) BD41(16.664,-18.074) BD42(17.31,-18.061) D2(0.637,-1.391) D44(18.061,-1.315) E44(18.074,-1.96)
  round 0.406 smd: B5(1.96,-0.586) BB4(1.391,-17.302) BB42(17.302,-17.233) D4(1.323,-1.391) D42(17.233,-1.323)
DMN3030LSS-13_SOP8L-8
  oval 0.635x1.829 smd: 1(0,0) 2(1.27,0) 3(2.54,0) 4(3.81,0) 5(3.81,5.17) 6(2.54,5.17) 7(1.27,5.17) 8(0,5.17)
DTA144EUA_SC70-3
  rect 0.813x0.914 smd: 1(0,0) 2(0.65,1.6) 3(-0.65,1.6)
DTC115EUA_SC70-3
  oval 0.813x0.914 smd: 1(0,0) 2(0.65,1.6) 3(-0.65,1.6)
DTC124EKAT146_SC59-3
  oval 1.016x1.524 smd: 1(0,0) 2(0.965,2.083) 3(-0.965,2.083)
F_451012MRL
  rect 1.956x3.15 smd: 1(0,0) 2(4.91,0)
FIDUCIAL_C40M80
  round 1.016 smd: 1(0,0)
FOX_AS0A626-U4SN-7F_204P
  round 1.6 hole 1.6 unplated: (-1.75,4.1)
  round 1.092 hole 1.092 unplated: (65.05,4.1)
  oval 0.356x2.007 smd: 1(0,0) 2(0.3,8.2) 3(0.6,0) 4(0.9,8.2) 5(1.2,0) 6(1.5,8.2) 7(1.8,0) 8(2.1,8.2) 9(2.4,0) 10(2.7,8.2) 11(3,0) 12(3.3,8.2) 13(3.6,0) 14(3.9,8.2) 15(4.2,0) 16(4.5,8.2) 17(4.8,0) 18(5.1,8.2) 19(5.4,0) 20(5.7,8.2) 21(6,0) 22(6.3,8.2) 23(6.6,0) 24(6.9,8.2) 25(7.2,0) 26(7.5,8.2) 27(7.8,0) 28(8.1,8.2) 29(8.4,0) 30(8.7,8.2) 31(9,0) 32(9.3,8.2) 33(9.6,0) 34(9.9,8.2) 35(10.2,0) 36(10.5,8.2) 37(10.8,0) 38(11.1,8.2) 39(11.4,0) 40(11.7,8.2) 41(12,0) 42(12.3,8.2) 43(12.6,0) 44(12.9,8.2) 45(13.2,0) 46(13.5,8.2) 47(13.8,0) 48(14.1,8.2) 49(14.4,0) 50(14.7,8.2) 51(15,0) 52(15.3,8.2) 53(15.6,0) 54(15.9,8.2) 55(16.2,0) 56(16.5,8.2) 57(16.8,0) 58(17.1,8.2) 59(17.4,0) 60(17.7,8.2) 61(18,0) 62(18.3,8.2) 63(18.6,0) 64(18.9,8.2) 65(19.2,0) 66(19.5,8.2) 67(19.8,0) 68(20.1,8.2) 69(20.4,0) 70(20.7,8.2) 71(21,0) 72(21.3,8.2) 73(24,0) 74(24.3,8.2) 75(24.6,0) 76(24.9,8.2) 77(25.2,0) 78(25.5,8.2) 79(25.8,0) 80(26.1,8.2) 81(26.4,0) 82(26.7,8.2) 83(27,0) 84(27.3,8.2) 85(27.6,0) 86(27.9,8.2) 87(28.2,0) 88(28.5,8.2) 89(28.8,0) 90(29.1,8.2) 91(29.4,0) 92(29.7,8.2) 93(30,0) 94(30.3,8.2) 95(30.6,0) 96(30.9,8.2) 97(31.2,0) 98(31.5,8.2) 99(31.8,0) 100(32.1,8.2) 101(32.4,0) 102(32.7,8.2) 103(33,0) 104(33.3,8.2) 105(33.6,0) 106(33.9,8.2) 107(34.2,0) 108(34.5,8.2) 109(34.8,0) 110(35.1,8.2) 111(35.4,0) 112(35.7,8.2) 113(36,0) 114(36.3,8.2) 115(36.6,0) 116(36.9,8.2) 117(37.2,0) 118(37.5,8.2) 119(37.8,0) 120(38.1,8.2) 121(38.4,0) 122(38.7,8.2) 123(39,0) 124(39.3,8.2) 125(39.6,0) 126(39.9,8.2) 127(40.2,0) 128(40.5,8.2) 129(40.8,0) 130(41.1,8.2) 131(41.4,0) 132(41.7,8.2) 133(42,0) 134(42.3,8.2) 135(42.6,0) 136(42.9,8.2) 137(43.2,0) 138(43.5,8.2) 139(43.8,0) 140(44.1,8.2) 141(44.4,0) 142(44.7,8.2) 143(45,0) 144(45.3,8.2) 145(45.6,0) 146(45.9,8.2) 147(46.2,0) 148(46.5,8.2) 149(46.8,0) 150(47.1,8.2) 151(47.4,0) 152(47.7,8.2) 153(48,0) 154(48.3,8.2) 155(48.6,0) 156(48.9,8.2) 157(49.2,0) 158(49.5,8.2) 159(49.8,0) 160(50.1,8.2) 161(50.4,0) 162(50.7,8.2) 163(51,0) 164(51.3,8.2) 165(51.6,0) 166(51.9,8.2) 167(52.2,0) 168(52.5,8.2) 169(52.8,0) 170(53.1,8.2) 171(53.4,0) 172(53.7,8.2) 173(54,0) 174(54.3,8.2) 175(54.6,0) 176(54.9,8.2) 177(55.2,0) 178(55.5,8.2) 179(55.8,0) 180(56.1,8.2) 181(56.4,0) 182(56.7,8.2) 183(57,0) 184(57.3,8.2) 185(57.6,0) 186(57.9,8.2) 187(58.2,0) 188(58.5,8.2) 189(58.8,0) 190(59.1,8.2) 191(59.4,0) 192(59.7,8.2) 193(60,0) 194(60.3,8.2) 195(60.6,0) 196(60.9,8.2) 197(61.2,0) 198(61.5,8.2) 199(61.8,0) 200(62.1,8.2) 201(62.4,0) 202(62.7,8.2) 203(63,0) 204(63.3,8.2)
  rect 3.505x4.597 smd: 205(-1.15,16.1) 206(64.45,16.1)
FOX_AS0A626-U8SN-7F_204P
  round 1.6 hole 1.6 unplated: (-1.75,4.1)
  round 1.092 hole 1.092 unplated: (65.05,4.1)
  oval 0.356x2.007 smd: 1(0,0) 2(0.3,8.2) 3(0.6,0) 4(0.9,8.2) 5(1.2,0) 6(1.5,8.2) 7(1.8,0) 8(2.1,8.2) 9(2.4,0) 10(2.7,8.2) 11(3,0) 12(3.3,8.2) 13(3.6,0) 14(3.9,8.2) 15(4.2,0) 16(4.5,8.2) 17(4.8,0) 18(5.1,8.2) 19(5.4,0) 20(5.7,8.2) 21(6,0) 22(6.3,8.2) 23(6.6,0) 24(6.9,8.2) 25(7.2,0) 26(7.5,8.2) 27(7.8,0) 28(8.1,8.2) 29(8.4,0) 30(8.7,8.2) 31(9,0) 32(9.3,8.2) 33(9.6,0) 34(9.9,8.2) 35(10.2,0) 36(10.5,8.2) 37(10.8,0) 38(11.1,8.2) 39(11.4,0) 40(11.7,8.2) 41(12,0) 42(12.3,8.2) 43(12.6,0) 44(12.9,8.2) 45(13.2,0) 46(13.5,8.2) 47(13.8,0) 48(14.1,8.2) 49(14.4,0) 50(14.7,8.2) 51(15,0) 52(15.3,8.2) 53(15.6,0) 54(15.9,8.2) 55(16.2,0) 56(16.5,8.2) 57(16.8,0) 58(17.1,8.2) 59(17.4,0) 60(17.7,8.2) 61(18,0) 62(18.3,8.2) 63(18.6,0) 64(18.9,8.2) 65(19.2,0) 66(19.5,8.2) 67(19.8,0) 68(20.1,8.2) 69(20.4,0) 70(20.7,8.2) 71(21,0) 72(21.3,8.2) 73(24,0) 74(24.3,8.2) 75(24.6,0) 76(24.9,8.2) 77(25.2,0) 78(25.5,8.2) 79(25.8,0) 80(26.1,8.2) 81(26.4,0) 82(26.7,8.2) 83(27,0) 84(27.3,8.2) 85(27.6,0) 86(27.9,8.2) 87(28.2,0) 88(28.5,8.2) 89(28.8,0) 90(29.1,8.2) 91(29.4,0) 92(29.7,8.2) 93(30,0) 94(30.3,8.2) 95(30.6,0) 96(30.9,8.2) 97(31.2,0) 98(31.5,8.2) 99(31.8,0) 100(32.1,8.2) 101(32.4,0) 102(32.7,8.2) 103(33,0) 104(33.3,8.2) 105(33.6,0) 106(33.9,8.2) 107(34.2,0) 108(34.5,8.2) 109(34.8,0) 110(35.1,8.2) 111(35.4,0) 112(35.7,8.2) 113(36,0) 114(36.3,8.2) 115(36.6,0) 116(36.9,8.2) 117(37.2,0) 118(37.5,8.2) 119(37.8,0) 120(38.1,8.2) 121(38.4,0) 122(38.7,8.2) 123(39,0) 124(39.3,8.2) 125(39.6,0) 126(39.9,8.2) 127(40.2,0) 128(40.5,8.2) 129(40.8,0) 130(41.1,8.2) 131(41.4,0) 132(41.7,8.2) 133(42,0) 134(42.3,8.2) 135(42.6,0) 136(42.9,8.2) 137(43.2,0) 138(43.5,8.2) 139(43.8,0) 140(44.1,8.2) 141(44.4,0) 142(44.7,8.2) 143(45,0) 144(45.3,8.2) 145(45.6,0) 146(45.9,8.2) 147(46.2,0) 148(46.5,8.2) 149(46.8,0) 150(47.1,8.2) 151(47.4,0) 152(47.7,8.2) 153(48,0) 154(48.3,8.2) 155(48.6,0) 156(48.9,8.2) 157(49.2,0) 158(49.5,8.2) 159(49.8,0) 160(50.1,8.2) 161(50.4,0) 162(50.7,8.2) 163(51,0) 164(51.3,8.2) 165(51.6,0) 166(51.9,8.2) 167(52.2,0) 168(52.5,8.2) 169(52.8,0) 170(53.1,8.2) 171(53.4,0) 172(53.7,8.2) 173(54,0) 174(54.3,8.2) 175(54.6,0) 176(54.9,8.2) 177(55.2,0) 178(55.5,8.2) 179(55.8,0) 180(56.1,8.2) 181(56.4,0) 182(56.7,8.2) 183(57,0) 184(57.3,8.2) 185(57.6,0) 186(57.9,8.2) 187(58.2,0) 188(58.5,8.2) 189(58.8,0) 190(59.1,8.2) 191(59.4,0) 192(59.7,8.2) 193(60,0) 194(60.3,8.2) 195(60.6,0) 196(60.9,8.2) 197(61.2,0) 198(61.5,8.2) 199(61.8,0) 200(62.1,8.2) 201(62.4,0) 202(62.7,8.2) 203(63,0) 204(63.3,8.2)
  rect 4.496x4.597 smd: 205(-5.8,16.1) 206(69.1,16.1)
G547I2P81U_MSOP8
  oval 0.381x1.549 smd: 1(0,0) 2(0.65,0) 3(1.3,0) 4(1.95,0) 5(1.95,4.37) 6(1.3,4.37) 7(0.65,4.37) 8(0,4.37)
G9191-330T1U_SOT23-5
  oval 0.533x1.194 smd: 1(0,0) 2(0.95,0) 3(1.9,0) 4(1.9,3) 5(0,3)
H_2P5X3P5N
  oval 2.489x3.505 hole 2.489x3.505 unplated: (0,0)
H_2P8
  round 3.302 hole 2.794: 1(0,0)
H_3P0N
  round 2.997 hole 2.997 unplated: (0,0)
H_3P3
  round 3.81 hole 3.302: 1(0,0)
H_3P8
  round 4.318 hole 3.81: 1(0,0)
HB_A051020-SAHR21_10P
  oval 0.61x1.092 smd: 1(0,0) 2(1,0) 3(2,0) 4(3,0) 5(4,0) 6(5,0) 7(6,0) 8(7,0) 9(8,0) 10(9,0)
  rect 2.388x2.997 smd: 11(-2.9,-2.05) 12(11.9,-2.05)
HB_A091020-SAHR21_10P
  oval 0.61x1.499 smd: 1(0,0) 2(1,0) 3(2,0) 4(3,0) 5(4,0) 6(5,0) 7(6,0) 8(7,0) 9(8,0) 10(9,0)
  rect 2.489x2.21 smd: 11(-3,-3.15) 12(12,-3.15)
INTEL_HASWELL_947P-T
  round 0.508 smd: A2(0,1) A3(0,2) A33(0,32) A34(0,33) A35(0,34) AP1(33,0) AP35(33,34) AR1(34,0) AR2(34,1) AR34(34,33) AR35(34,34) AT1(35,0) AT2(35,1) AT3(35,2) AT33(35,32) AT34(35,33) AT35(35,34) B1(1,0) B2(1,1) B34(1,33) B35(1,34) C1(2,0) C35(2,34)
  oval 0.61x0.457 smd: A4(0,3) A5(0,4) A6(0,5) A7(0,6) A8(0,7) A9(0,8) A10(0,9) A11(0,10) A12(0,11) A13(0,12) A14(0,13) A15(0,14) A16(0,15) A17(0,16) A18(0,17) A19(0,18) A20(0,19) A21(0,20) A22(0,21) A23(0,22) A24(0,23) A25(0,24) A26(0,25) A27(0,26) A28(0,27) A29(0,28) A30(0,29) A31(0,30) A32(0,31) AT4(35,3) AT5(35,4) AT6(35,5) AT7(35,6) AT8(35,7) AT9(35,8) AT10(35,9) AT11(35,10) AT12(35,11) AT13(35,12) AT14(35,13) AT15(35,14) AT16(35,15) AT17(35,16) AT18(35,17) AT19(35,18) AT20(35,19) AT21(35,20) AT22(35,21) AT23(35,22) AT24(35,23) AT25(35,24) AT26(35,25) AT27(35,26) AT28(35,27) AT29(35,28) AT30(35,29) AT31(35,30) AT32(35,31)
  oval 0.457x0.61 smd: AA1(20,0) AA35(20,34) AB1(21,0) AB35(21,34) AC1(22,0) AC35(22,34) AD1(23,0) AD35(23,34) AE1(24,0) AE35(24,34) AF1(25,0) AF35(25,34) AG1(26,0) AG35(26,34) AH1(27,0) AH35(27,34) AJ1(28,0) AJ35(28,34) AK1(29,0) AK35(29,34) AL1(30,0) AL35(30,34) AM1(31,0) AM35(31,34) AN1(32,0) AN35(32,34) D1(3,0) D35(3,34) E1(4,0) E35(4,34) F1(5,0) F35(5,34) G1(6,0) G35(6,34) H1(7,0) H35(7,34) J1(8,0) J35(8,34) K1(9,0) K35(9,34) L1(10,0) L35(10,34) M1(11,0) M35(11,34) N1(12,0) N35(12,34) P1(13,0) P35(13,34) R1(14,0) R35(14,34) T1(15,0) T35(15,34) U1(16,0) U35(16,34) V1(17,0) V35(17,34) W1(18,0) W35(18,34) Y1(19,0) Y35(19,34)
  round 0.457 smd: AA2(20,1) AA3(20,2) AA4(20,3) AA5(20,4) AA6(20,5) AA7(20,6) AA8(20,7) AA9(20,8) AA10(20,9) AA11(20,10) AA25(20,24) AA26(20,25) AA27(20,26) AA28(20,27) AA29(20,28) AA30(20,29) AA31(20,30) AA32(20,31) AA33(20,32) AA34(20,33) AB2(21,1) AB3(21,2) AB4(21,3) AB5(21,4) AB6(21,5) AB7(21,6) AB8(21,7) AB9(21,8) AB10(21,9) AB11(21,10) AB25(21,24) AB26(21,25) AB27(21,26) AB28(21,27) AB29(21,28) AB30(21,29) AB31(21,30) AB32(21,31) AB33(21,32) AB34(21,33) AC2(22,1) AC3(22,2) AC4(22,3) AC5(22,4) AC6(22,5) AC7(22,6) AC8(22,7) AC9(22,8) AC10(22,9) AC11(22,10) AC25(22,24) AC26(22,25) AC27(22,26) AC28(22,27) AC29(22,28) AC30(22,29) AC31(22,30) AC32(22,31) AC33(22,32) AC34(22,33) AD2(23,1) AD3(23,2) AD4(23,3) AD5(23,4) AD6(23,5) AD7(23,6) AD8(23,7) AD9(23,8) AD10(23,9) AD11(23,10) AD25(23,24) AD26(23,25) AD27(23,26) AD28(23,27) AD29(23,28) AD30(23,29) AD31(23,30) AD32(23,31) AD33(23,32) AD34(23,33) AE2(24,1) AE3(24,2) AE4(24,3) AE5(24,4) AE6(24,5) AE7(24,6) AE8(24,7) AE9(24,8) AE10(24,9) AE11(24,10) AE25(24,24) AE26(24,25) AE27(24,26) AE28(24,27) AE29(24,28) AE30(24,29) AE31(24,30) AE32(24,31) AE33(24,32) AE34(24,33) AF2(25,1) AF3(25,2) AF4(25,3) AF5(25,4) AF6(25,5) AF7(25,6) AF8(25,7) AF9(25,8) AF10(25,9) AF11(25,10) AF25(25,24) AF26(25,25) AF27(25,26) AF28(25,27) AF29(25,28) AF30(25,29) AF31(25,30) AF32(25,31) AF33(25,32) AF34(25,33) AG2(26,1) AG3(26,2) AG4(26,3) AG5(26,4) AG6(26,5) AG7(26,6) AG8(26,7) AG9(26,8) AG10(26,9) AG11(26,10) AG25(26,24) AG26(26,25) AG27(26,26) AG28(26,27) AG29(26,28) AG30(26,29) AG31(26,30) AG32(26,31) AG33(26,32) AG34(26,33) AH2(27,1) AH3(27,2) AH4(27,3) AH5(27,4) AH6(27,5) AH7(27,6) AH8(27,7) AH9(27,8) AH10(27,9) AH11(27,10) AH25(27,24) AH26(27,25) AH27(27,26) AH28(27,27) AH29(27,28) AH30(27,29) AH31(27,30) AH32(27,31) AH33(27,32) AH34(27,33) AJ2(28,1) AJ3(28,2) AJ4(28,3) AJ5(28,4) AJ6(28,5) AJ7(28,6) AJ8(28,7) AJ9(28,8) AJ10(28,9) AJ11(28,10) AJ25(28,24) AJ26(28,25) AJ27(28,26) AJ28(28,27) AJ29(28,28) AJ30(28,29) AJ31(28,30) AJ32(28,31) AJ33(28,32) AJ34(28,33) AK2(29,1) AK3(29,2) AK4(29,3) AK5(29,4) AK6(29,5) AK7(29,6) AK8(29,7) AK9(29,8) AK10(29,9) AK11(29,10) AK25(29,24) AK26(29,25) AK27(29,26) AK28(29,27) AK29(29,28) AK30(29,29) AK31(29,30) AK32(29,31) AK33(29,32) AK34(29,33) AL2(30,1) AL3(30,2) AL4(30,3) AL5(30,4) AL6(30,5) AL7(30,6) AL8(30,7) AL9(30,8) AL10(30,9) AL11(30,10) AL12(30,11) AL13(30,12) AL14(30,13) AL15(30,14) AL16(30,15) AL17(30,16) AL18(30,17) AL19(30,18) AL20(30,19) AL21(30,20) AL22(30,21) AL23(30,22) AL24(30,23) AL25(30,24) AL26(30,25) AL27(30,26) AL28(30,27) AL29(30,28) AL30(30,29) AL31(30,30) AL32(30,31) AL33(30,32) AL34(30,33) AM2(31,1) AM3(31,2) AM4(31,3) AM5(31,4) AM6(31,5) AM7(31,6) AM8(31,7) AM9(31,8) AM10(31,9) AM11(31,10) AM12(31,11) AM13(31,12) AM14(31,13) AM15(31,14) AM16(31,15) AM17(31,16) AM18(31,17) AM19(31,18) AM20(31,19) AM21(31,20) AM22(31,21) AM23(31,22) AM24(31,23) AM25(31,24) AM26(31,25) AM27(31,26) AM28(31,27) AM29(31,28) AM30(31,29) AM31(31,30) AM32(31,31) AM33(31,32) AM34(31,33) AN2(32,1) AN3(32,2) AN4(32,3) AN5(32,4) AN6(32,5) AN7(32,6) AN8(32,7) AN9(32,8) AN10(32,9) AN11(32,10) AN12(32,11) AN13(32,12) AN14(32,13) AN15(32,14) AN16(32,15) AN17(32,16) AN18(32,17) AN19(32,18) AN20(32,19) AN21(32,20) AN22(32,21) AN23(32,22) AN24(32,23) AN25(32,24) AN26(32,25) AN27(32,26) AN28(32,27) AN29(32,28) AN30(32,29) AN31(32,30) AN32(32,31) AN33(32,32) AN34(32,33) AP2(33,1) AP3(33,2) AP4(33,3) AP5(33,4) AP6(33,5) AP7(33,6) AP8(33,7) AP9(33,8) AP10(33,9) AP11(33,10) AP12(33,11) AP13(33,12) AP14(33,13) AP15(33,14) AP16(33,15) AP17(33,16) AP18(33,17) AP19(33,18) AP20(33,19) AP21(33,20) AP22(33,21) AP23(33,22) AP24(33,23) AP25(33,24) AP26(33,25) AP27(33,26) AP28(33,27) AP29(33,28) AP30(33,29) AP31(33,30) AP32(33,31) AP33(33,32) AP34(33,33) AR3(34,2) AR4(34,3) AR5(34,4) AR6(34,5) AR7(34,6) AR8(34,7) AR9(34,8) AR10(34,9) AR11(34,10) AR12(34,11) AR13(34,12) AR14(34,13) AR15(34,14) AR16(34,15) AR17(34,16) AR18(34,17) AR19(34,18) AR20(34,19) AR21(34,20) AR22(34,21) AR23(34,22) AR24(34,23) AR25(34,24) AR26(34,25) AR27(34,26) AR28(34,27) AR29(34,28) AR30(34,29) AR31(34,30) AR32(34,31) AR33(34,32) B3(1,2) B4(1,3) B5(1,4) B6(1,5) B7(1,6) B8(1,7) B9(1,8) B10(1,9) B11(1,10) B12(1,11) B13(1,12) B14(1,13) B15(1,14) B16(1,15) B17(1,16) B18(1,17) B19(1,18) B20(1,19) B21(1,20) B22(1,21) B23(1,22) B24(1,23) B25(1,24) B26(1,25) B27(1,26) B28(1,27) B29(1,28) B30(1,29) B31(1,30) B32(1,31) B33(1,32) C2(2,1) C3(2,2) C4(2,3) C5(2,4) C6(2,5) C7(2,6) C8(2,7) C9(2,8) C10(2,9) C11(2,10) C12(2,11) C13(2,12) C14(2,13) C15(2,14) C16(2,15) C17(2,16) C18(2,17) C19(2,18) C20(2,19) C21(2,20) C22(2,21) C23(2,22) C24(2,23) C25(2,24) C26(2,25) C27(2,26) C28(2,27) C29(2,28) C30(2,29) C31(2,30) C32(2,31) C33(2,32) C34(2,33) D2(3,1) D3(3,2) D4(3,3) D5(3,4) D6(3,5) D7(3,6) D8(3,7) D9(3,8) D10(3,9) D11(3,10) D12(3,11) D13(3,12) D14(3,13) D15(3,14) D16(3,15) D17(3,16) D18(3,17) D19(3,18) D20(3,19) D21(3,20) D22(3,21) D23(3,22) D24(3,23) D25(3,24) D26(3,25) D27(3,26) D28(3,27) D29(3,28) D30(3,29) D31(3,30) D32(3,31) D33(3,32) D34(3,33) E2(4,1) E3(4,2) E4(4,3) E5(4,4) E6(4,5) E7(4,6) E8(4,7) E9(4,8) E10(4,9) E11(4,10) E12(4,11) E13(4,12) E14(4,13) E15(4,14) E16(4,15) E17(4,16) E18(4,17) E19(4,18) E20(4,19) E21(4,20) E22(4,21) E23(4,22) E24(4,23) E25(4,24) E26(4,25) E27(4,26) E28(4,27) E29(4,28) E30(4,29) E31(4,30) E32(4,31) E33(4,32) E34(4,33) F2(5,1) F3(5,2) F4(5,3) F5(5,4) F6(5,5) F7(5,6) F8(5,7) F9(5,8) F10(5,9) F11(5,10) F12(5,11) F13(5,12) F14(5,13) F15(5,14) F16(5,15) F17(5,16) F18(5,17) F19(5,18) F20(5,19) F21(5,20) F22(5,21) F23(5,22) F24(5,23) F25(5,24) F26(5,25) F27(5,26) F28(5,27) F29(5,28) F30(5,29) F31(5,30) F32(5,31) F33(5,32) F34(5,33) G2(6,1) G3(6,2) G4(6,3) G5(6,4) G6(6,5) G7(6,6) G8(6,7) G9(6,8) G10(6,9) G11(6,10) G25(6,24) G26(6,25) G27(6,26) G28(6,27) G29(6,28) G30(6,29) G31(6,30) G32(6,31) G33(6,32) G34(6,33) H2(7,1) H3(7,2) H4(7,3) H5(7,4) H6(7,5) H7(7,6) H8(7,7) H9(7,8) H10(7,9) H11(7,10) H25(7,24) H26(7,25) H27(7,26) H28(7,27) H29(7,28) H30(7,29) H31(7,30) H32(7,31) H33(7,32) H34(7,33) J2(8,1) J3(8,2) J4(8,3) J5(8,4) J6(8,5) J7(8,6) J8(8,7) J9(8,8) J10(8,9) J11(8,10) J25(8,24) J26(8,25) J27(8,26) J28(8,27) J29(8,28) J30(8,29) J31(8,30) J32(8,31) J33(8,32) J34(8,33) K2(9,1) K3(9,2) K4(9,3) K5(9,4) K6(9,5) K7(9,6) K8(9,7) K9(9,8) K10(9,9) K11(9,10) K25(9,24) K26(9,25) K27(9,26) K28(9,27) K29(9,28) K30(9,29) K31(9,30) K32(9,31) K33(9,32) K34(9,33) L2(10,1) L3(10,2) L4(10,3) L5(10,4) L6(10,5) L7(10,6) L8(10,7) L9(10,8) L10(10,9) L11(10,10) L25(10,24) L26(10,25) L27(10,26) L28(10,27) L29(10,28) L30(10,29) L31(10,30) L32(10,31) L33(10,32) L34(10,33) M2(11,1) M3(11,2) M4(11,3) M5(11,4) M6(11,5) M7(11,6) M8(11,7) M9(11,8) M10(11,9) M11(11,10) M25(11,24) M26(11,25) M27(11,26) M28(11,27) M29(11,28) M30(11,29) M31(11,30) M32(11,31) M33(11,32) M34(11,33) N2(12,1) N3(12,2) N4(12,3) N5(12,4) N6(12,5) N7(12,6) N8(12,7) N9(12,8) N10(12,9) N11(12,10) N25(12,24) N26(12,25) N27(12,26) N28(12,27) N29(12,28) N30(12,29) N31(12,30) N32(12,31) N33(12,32) N34(12,33) P2(13,1) P3(13,2) P4(13,3) P5(13,4) P6(13,5) P7(13,6) P8(13,7) P9(13,8) P10(13,9) P11(13,10) P25(13,24) P26(13,25) P27(13,26) P28(13,27) P29(13,28) P30(13,29) P31(13,30) P32(13,31) P33(13,32) P34(13,33) R2(14,1) R3(14,2) R4(14,3) R5(14,4) R6(14,5) R7(14,6) R8(14,7) R9(14,8) R10(14,9) R11(14,10) R25(14,24) R26(14,25) R27(14,26) R28(14,27) R29(14,28) R30(14,29) R31(14,30) R32(14,31) R33(14,32) R34(14,33) T2(15,1) T3(15,2) T4(15,3) T5(15,4) T6(15,5) T7(15,6) T8(15,7) T9(15,8) T10(15,9) T11(15,10) T25(15,24) T26(15,25) T27(15,26) T28(15,27) T29(15,28) T30(15,29) T31(15,30) T32(15,31) T33(15,32) T34(15,33) U2(16,1) U3(16,2) U4(16,3) U5(16,4) U6(16,5) U7(16,6) U8(16,7) U9(16,8) U10(16,9) U11(16,10) U25(16,24) U26(16,25) U27(16,26) U28(16,27) U29(16,28) U30(16,29) U31(16,30) U32(16,31) U33(16,32) U34(16,33) V2(17,1) V3(17,2) V4(17,3) V5(17,4) V6(17,5) V7(17,6) V8(17,7) V9(17,8) V10(17,9) V11(17,10) V25(17,24) V26(17,25) V27(17,26) V28(17,27) V29(17,28) V30(17,29) V31(17,30) V32(17,31) V33(17,32) V34(17,33) W2(18,1) W3(18,2) W4(18,3) W5(18,4) W6(18,5) W7(18,6) W8(18,7) W9(18,8) W10(18,9) W11(18,10) W25(18,24) W26(18,25) W27(18,26) W28(18,27) W29(18,28) W30(18,29) W31(18,30) W32(18,31) W33(18,32) W34(18,33) Y2(19,1) Y3(19,2) Y4(19,3) Y5(19,4) Y6(19,5) Y7(19,6) Y8(19,7) Y9(19,8) Y10(19,9) Y11(19,10) Y25(19,24) Y26(19,25) Y27(19,26) Y28(19,27) Y29(19,28) Y30(19,29) Y31(19,30) Y32(19,31) Y33(19,32) Y34(19,33)
ISL62883CHRTZ-T_TQFN40_5X5
  oval 0.203x0.991 smd: 1(0,0) 2(0.4,0) 3(0.8,0) 4(1.2,0) 5(1.6,0) 6(2,0) 7(2.4,0) 8(2.8,0) 9(3.2,0) 10(3.6,0) 21(3.6,4.95) 22(3.2,4.95) 23(2.8,4.95) 24(2.4,4.95) 25(2,4.95) 26(1.6,4.95) 27(1.2,4.95) 28(0.8,4.95) 29(0.4,4.95) 30(0,4.95)
  oval 0.991x0.203 smd: 11(4.275,0.675) 12(4.275,1.075) 13(4.275,1.475) 14(4.275,1.875) 15(4.275,2.275) 16(4.275,2.675) 17(4.275,3.075) 18(4.275,3.475) 19(4.275,3.875) 20(4.275,4.275) 31(-0.675,4.275) 32(-0.675,3.875) 33(-0.675,3.475) 34(-0.675,3.075) 35(-0.675,2.675) 36(-0.675,2.275) 37(-0.675,1.875) 38(-0.675,1.475) 39(-0.675,1.075) 40(-0.675,0.675)
  rect 3.505x3.505 smd: 41(1.8,2.475)
JUMP_43X39
  custom 0.191x0.191 smd: 1(0,0) 2(0.914,0)
JUMP_43X79
  custom 0.188x0.188 smd: 1(0,0) 2(1.1,0)
JUMP_43X118
  custom 0.187x0.187 smd: 1(0,0) 2(1.1,0)
K4W4G1646B-HC11_FBGA_96P_A39
  round 0.445 smd: A1(0,0) A2(0.8,0) A3(1.6,0) A7(4.801,0) A8(5.601,0) A9(6.401,0) B1(0,-0.8) B2(0.8,-0.8) B3(1.6,-0.8) B7(4.801,-0.8) B8(5.601,-0.8) B9(6.401,-0.8) C1(0,-1.6) C2(0.8,-1.6) C3(1.6,-1.6) C7(4.801,-1.6) C8(5.601,-1.6) C9(6.401,-1.6) D1(0,-2.4) D2(0.8,-2.4) D3(1.6,-2.4) D7(4.801,-2.4) D8(5.601,-2.4) D9(6.401,-2.4) E1(0,-3.2) E2(0.8,-3.2) E3(1.6,-3.2) E7(4.801,-3.2) E8(5.601,-3.2) E9(6.401,-3.2) M1(0,-8.801) M2(0.8,-8.801) M3(1.6,-8.801) M7(4.801,-8.801) M8(5.601,-8.801) M9(6.401,-8.801) N1(0,-9.601) N2(0.8,-9.601) N3(1.6,-9.601) N7(4.801,-9.601) N8(5.601,-9.601) N9(6.401,-9.601) P1(0,-10.401) P2(0.8,-10.401) P3(1.6,-10.401) P7(4.801,-10.401) P8(5.601,-10.401) P9(6.401,-10.401) R1(0,-11.201) R2(0.8,-11.201) R3(1.6,-11.201) R7(4.801,-11.201) R8(5.601,-11.201) R9(6.401,-11.201) T1(0,-12.002) T2(0.8,-12.002) T3(1.6,-12.002) T7(4.801,-12.002) T8(5.601,-12.002) T9(6.401,-12.002)
  round 0.343 smd: F1(0,-4) F2(0.8,-4) F3(1.6,-4) F7(4.801,-4) F8(5.601,-4) F9(6.401,-4) G1(0,-4.801) G2(0.8,-4.801) G3(1.6,-4.801) G7(4.801,-4.801) G8(5.601,-4.801) G9(6.401,-4.801) H1(0,-5.601) H2(0.8,-5.601) H3(1.6,-5.601) H7(4.801,-5.601) H8(5.601,-5.601) H9(6.401,-5.601) J1(0,-6.401) J2(0.8,-6.401) J3(1.6,-6.401) J7(4.801,-6.401) J8(5.601,-6.401) J9(6.401,-6.401) K1(0,-7.201) K2(0.8,-7.201) K3(1.6,-7.201) K7(4.801,-7.201) K8(5.601,-7.201) K9(6.401,-7.201) L1(0,-8.001) L2(0.8,-8.001) L3(1.6,-8.001) L7(4.801,-8.001) L8(5.601,-8.001) L9(6.401,-8.001)
KARSO_KJ1040-3R3M_2P
  rect 3.81x3.988 smd: 1(0,0) 2(9.2,0)
KB9012QF-A2_LQFP128_14X14
  oval 0.203x1.753 smd: 1(0,0) 2(0.4,0) 3(0.8,0) 4(1.2,0) 5(1.6,0) 6(2,0) 7(2.4,0) 8(2.8,0) 9(3.2,0) 10(3.6,0) 11(4,0) 12(4.4,0) 13(4.8,0) 14(5.2,0) 15(5.6,0) 16(6,0) 17(6.4,0) 18(6.8,0) 19(7.2,0) 20(7.6,0) 21(8,0) 22(8.4,0) 23(8.8,0) 24(9.2,0) 25(9.6,0) 26(10,0) 27(10.4,0) 28(10.8,0) 29(11.2,0) 30(11.6,0) 31(12,0) 32(12.4,0) 65(12.4,15.654) 66(12,15.654) 67(11.6,15.654) 68(11.2,15.654) 69(10.8,15.654) 70(10.4,15.654) 71(10,15.654) 72(9.6,15.654) 73(9.2,15.654) 74(8.8,15.654) 75(8.4,15.654) 76(8,15.654) 77(7.6,15.654) 78(7.2,15.654) 79(6.8,15.654) 80(6.4,15.654) 81(6,15.654) 82(5.6,15.654) 83(5.2,15.654) 84(4.8,15.654) 85(4.4,15.654) 86(4,15.654) 87(3.6,15.654) 88(3.2,15.654) 89(2.8,15.654) 90(2.4,15.654) 91(2,15.654) 92(1.6,15.654) 93(1.2,15.654) 94(0.8,15.654) 95(0.4,15.654) 96(0,15.654)
  oval 1.753x0.203 smd: 33(14.027,1.627) 34(14.027,2.027) 35(14.027,2.427) 36(14.027,2.827) 37(14.027,3.227) 38(14.027,3.627) 39(14.027,4.027) 40(14.027,4.427) 41(14.027,4.827) 42(14.027,5.227) 43(14.027,5.627) 44(14.027,6.027) 45(14.027,6.427) 46(14.027,6.827) 47(14.027,7.227) 48(14.027,7.627) 49(14.027,8.027) 50(14.027,8.427) 51(14.027,8.827) 52(14.027,9.227) 53(14.027,9.627) 54(14.027,10.027) 55(14.027,10.427) 56(14.027,10.827) 57(14.027,11.227) 58(14.027,11.627) 59(14.027,12.027) 60(14.027,12.427) 61(14.027,12.827) 62(14.027,13.227) 63(14.027,13.627) 64(14.027,14.027) 97(-1.627,14.027) 98(-1.627,13.627) 99(-1.627,13.227) 100(-1.627,12.827) 101(-1.627,12.427) 102(-1.627,12.027) 103(-1.627,11.627) 104(-1.627,11.227) 105(-1.627,10.827) 106(-1.627,10.427) 107(-1.627,10.027) 108(-1.627,9.627) 109(-1.627,9.227) 110(-1.627,8.827) 111(-1.627,8.427) 112(-1.627,8.027) 113(-1.627,7.627) 114(-1.627,7.227) 115(-1.627,6.827) 116(-1.627,6.427) 117(-1.627,6.027) 118(-1.627,5.627) 119(-1.627,5.227) 120(-1.627,4.827) 121(-1.627,4.427) 122(-1.627,4.027) 123(-1.627,3.627) 124(-1.627,3.227) 125(-1.627,2.827) 126(-1.627,2.427) 127(-1.627,2.027) 128(-1.627,1.627)
KC_FBMA-L11-160808-121LMT_2P
  rect 0.889x1.092 smd: 1(0,0) 2(1.5,0)
KC_FBMA-L11-201209-221LMA30_2P
  rect 0.838x1.397 smd: 1(0,0) 2(1.65,0)
KC_FBMA-L11160808601LMA10T_2P
  rect 0.559x1.041 smd: 1(0,0) 2(1.3,0)
KING_WCM-2012-900T_4P
  rect 0.889x0.406 smd: 1(0,0) 2(1.7,0) 3(1.7,0.8) 4(0,0.8)
L_1812-1806
  oval 1.016x3.708 smd: 1(0,0) 2(4.013,0)
L_FBM-11-160808_2P
  oval 0.864x1.219 smd: 1(0,0) 2(1.422,0)
LED_19-213A-T1D-CP2Q2HY-3T_2P
  rect 0.787x0.787 smd: 1(0,0) 2(1.5,0)
LM393DG_SO8
  oval 0.635x1.854 smd: 1(0,0) 2(1.27,0) 3(2.54,0) 4(3.81,0) 5(3.81,5.165) 6(2.54,5.165) 7(1.27,5.165) 8(0,5.165)
MARS-PRO_FCBGA_962P_A39
  round 0.61 smd: A3(0.8,0) A37(26.8,0) A39(27.6,0) AU1(0,-26.8) AU3(0.8,-26.8) AU37(26.8,-26.8) AU39(27.6,-26.8) AW1(0,-27.6) AW3(0.8,-27.6) AW37(26.8,-27.6) AW39(27.6,-27.6) C1(0,-0.8) C3(0.8,-0.8) C37(26.8,-0.8) C39(27.6,-0.8)
  round 0.406 smd: A5(1.7,0) A6(2.6,0) A34(25,0) A35(25.9,0) AA7(3.2,-15) AA8(4,-15) AA32(23.6,-15) AA33(24.4,-15) AC7(3.2,-16.2) AC8(4,-16.2) AC9(4.8,-16.2) AC31(22.8,-16.2) AC32(23.6,-16.2) AC33(24.4,-16.2) AD7(3.2,-17.4) AD8(4,-17.4) AD9(4.8,-17.4) AD10(5.6,-17.4) AD30(22,-17.4) AD31(22.8,-17.4) AD32(23.6,-17.4) AD33(24.4,-17.4) AF7(3.2,-18.6) AF8(4,-18.6) AF9(4.8,-18.6) AF10(5.6,-18.6) AF11(6.4,-18.4) AF29(21.2,-18.6) AF30(22,-18.6) AF31(22.8,-18.6) AF32(23.6,-18.6) AF33(24.4,-18.6) AG7(3.2,-19.8) AG8(4,-19.8) AG9(4.8,-19.8) AG10(5.6,-19.8) AG11(6.4,-19.4) AG12(7.4,-19.4) AG28(20.4,-19.4) AG29(21.2,-19.8) AG30(22,-19.8) AG31(22.8,-19.8) AG32(23.6,-19.8) AG33(24.4,-19.8) AH11(6.4,-20.4) AH12(7.4,-20.4) AH28(20.4,-20.4) AH29(21.2,-20.6) AJ7(3.2,-21) AJ8(4,-21) AJ9(4.8,-21) AJ10(5.6,-21) AJ11(6.6,-21.2) AJ28(20.6,-21.2) AJ30(22,-21) AJ31(22.8,-21) AJ32(23.6,-21) AJ33(24.4,-21) AK7(3.2,-22) AK8(4,-22) AK9(4.8,-22) AK10(5.6,-22) AK11(6.6,-22) AK13(7.8,-22) AK14(9,-22) AK16(10.2,-22) AK24(17.4,-22) AK26(18.6,-22) AK27(19.8,-22) AK29(21,-22) AK30(22,-22) AK31(22.8,-22) AK32(23.6,-22) AK33(24.4,-22) AL7(3.2,-22.8) AL8(4,-22.8) AL9(4.8,-22.8) AL10(5.6,-22.8) AL11(6.6,-22.8) AL13(7.8,-22.8) AL14(9,-22.8) AL16(10.2,-22.8) AL17(11.4,-22.8) AL23(16.2,-22.8) AL24(17.4,-22.8) AL26(18.6,-22.8) AL27(19.8,-22.8) AL29(21,-22.8) AL30(22,-22.8) AL31(22.8,-22.8) AL32(23.6,-22.8) AL33(24.4,-22.8) AM7(3.2,-23.6) AM8(4,-23.6) AM9(4.8,-23.6) AM10(5.6,-23.6) AM11(6.6,-23.6) AM13(7.8,-23.6) AM14(9,-23.6) AM16(10.2,-23.6) AM17(11.4,-23.6) AM19(12.6,-23.6) AM21(15,-23.6) AM23(16.2,-23.6) AM24(17.4,-23.6) AM26(18.6,-23.6) AM27(19.8,-23.6) AM29(21,-23.6) AM30(22,-23.6) AM31(22.8,-23.6) AM32(23.6,-23.6) AM33(24.4,-23.6) AN2(0.4,-24.2) AN4(1.2,-24.2) AN6(2.4,-24.4) AN8(4,-24.4) AN9(4.8,-24.4) AN10(5.6,-24.4) AN11(6.6,-24.4) AN13(7.8,-24.4) AN14(9,-24.4) AN16(10.2,-24.4) AN17(11.4,-24.4) AN19(12.6,-24.4) AN20(13.8,-24.4) AN21(15,-24.4) AN23(16.2,-24.4) AN24(17.4,-24.4) AN26(18.6,-24.4) AN27(19.8,-24.4) AN29(21,-24.4) AN30(22,-24.4) AN31(22.8,-24.4) AN32(23.6,-24.4) AN34(25.2,-24.4) AN36(26.4,-24.2) AN38(27.2,-24.2) AP1(0,-25) AP3(0.8,-25) AP5(1.6,-25) AP6(2.4,-25.2) AP7(3.2,-25.2) AP33(24.4,-25.2) AP34(25.2,-25.2) AP35(26,-25) AP37(26.8,-25) AP39(27.6,-25) AR1(0,-25.9) AR3(0.8,-25.9) AR5(1.7,-25.9) AR6(2.6,-26) AR34(25,-26) AR35(25.9,-25.9) AR37(26.8,-25.9) AR39(27.6,-25.9) AT7(3.4,-26.4) AT33(24.2,-26.4) AU5(1.7,-26.8) AU6(2.6,-26.8) AU34(25,-26.8) AU35(25.9,-26.8) AV7(3.4,-27.2) AV33(24.2,-27.2) AW5(1.7,-27.6) AW6(2.6,-27.6) AW34(25,-27.6) AW35(25.9,-27.6) B7(3.4,-0.4) B33(24.2,-0.4) C5(1.7,-0.8) C6(2.6,-0.8) C34(25,-0.8) C35(25.9,-0.8) D7(3.4,-1.2) D33(24.2,-1.2) E1(0,-1.7) E3(0.8,-1.7) E5(1.7,-1.7) E6(2.6,-1.6) E34(25,-1.6) E35(25.9,-1.7) E37(26.8,-1.7) E39(27.6,-1.7) F1(0,-2.6) F3(0.8,-2.6) F5(1.6,-2.6) F6(2.4,-2.4) F7(3.2,-2.4) F33(24.4,-2.4) F34(25.2,-2.4) F35(26,-2.6) F37(26.8,-2.6) F39(27.6,-2.6) G2(0.4,-3.4) G4(1.2,-3.4) G6(2.4,-3.2) G8(4,-3.2) G9(4.8,-3.2) G10(5.6,-3.2) G11(6.6,-3.2) G13(7.8,-3.2) G14(9,-3.2) G16(10.2,-3.2) G17(11.4,-3.2) G19(12.6,-3.2) G20(13.8,-3.2) G21(15,-3.2) G23(16.2,-3.2) G24(17.4,-3.2) G26(18.6,-3.2) G27(19.8,-3.2) G29(21,-3.2) G30(22,-3.2) G31(22.8,-3.2) G32(23.6,-3.2) G34(25.2,-3.2) G36(26.4,-3.4) G38(27.2,-3.4) H7(3.2,-4) H8(4,-4) H9(4.8,-4) H10(5.6,-4) H11(6.6,-4) H13(7.8,-4) H14(9,-4) H16(10.2,-4) H17(11.4,-4) H19(12.6,-4) H21(15,-4) H23(16.2,-4) H24(17.4,-4) H26(18.6,-4) H27(19.8,-4) H29(21,-4) H30(22,-4) H31(22.8,-4) H32(23.6,-4) H33(24.4,-4) J7(3.2,-4.8) J8(4,-4.8) J9(4.8,-4.8) J10(5.6,-4.8) J11(6.6,-4.8) J13(7.8,-4.8) J14(9,-4.8) J16(10.2,-4.8) J17(11.4,-4.8) J23(16.2,-4.8) J24(17.4,-4.8) J26(18.6,-4.8) J27(19.8,-4.8) J29(21,-4.8) J30(22,-4.8) J31(22.8,-4.8) J32(23.6,-4.8) J33(24.4,-4.8) K7(3.2,-5.6) K8(4,-5.6) K9(4.8,-5.6) K10(5.6,-5.6) K11(6.6,-5.6) K13(7.8,-5.6) K14(9,-5.6) K16(10.2,-5.6) K24(17.4,-5.6) K26(18.6,-5.6) K27(19.8,-5.6) K29(21,-5.6) K30(22,-5.6) K31(22.8,-5.6) K32(23.6,-5.6) K33(24.4,-5.6) L7(3.2,-6.6) L8(4,-6.6) L9(4.8,-6.6) L10(5.6,-6.6) L11(6.4,-6.4) L12(7.4,-6.4) L28(20.4,-6.4) L29(21.2,-6.6) L30(22,-6.6) L31(22.8,-6.6) L32(23.6,-6.6) L33(24.4,-6.6) M11(6.4,-7.4) M12(7.4,-7.4) M28(20.4,-7.4) N7(3.2,-7.8) N8(4,-7.8) N9(4.8,-7.8) N10(5.6,-7.8) N11(6.4,-8.4) N12(7.4,-8.4) N28(20.4,-8.4) N29(21.2,-7.8) N30(22,-7.8) N31(22.8,-7.8) N32(23.6,-7.8) N33(24.4,-7.8) P7(3.2,-9) P8(4,-9) P9(4.8,-9) P10(5.6,-9) P29(21.2,-9) P30(22,-9) P31(22.8,-9) P32(23.6,-9) P33(24.4,-9) R11(6.4,-9.4) T7(3.2,-10.2) T8(4,-10.2) T9(4.8,-10.2) T10(5.6,-10.2) T30(22,-10.2) T31(22.8,-10.2) T32(23.6,-10.2) T33(24.4,-10.2) U7(3.2,-11.4) U8(4,-11.4) U9(4.8,-11.4) U31(22.8,-11.4) U32(23.6,-11.4) U33(24.4,-11.4) W7(3.2,-12.6) W8(4,-12.6) W32(23.6,-12.6) W33(24.4,-12.6) Y7(3.2,-13.8) Y33(24.4,-13.8)
  round 0.305 smd: A8(4.2,0) A10(5.8,0) A12(7.4,0) A14(9,0) A16(10.6,0) A18(12.2,0) A20(13.8,0) A22(15.4,0) A24(17,0) A26(18.6,0) A28(20.2,0) A30(21.8,0) A32(23.4,0) AA2(0.4,-14.6) AA4(1.2,-14.6) AA6(2.4,-14.8) AA34(25.2,-14.8) AA36(26.4,-14.6) AA38(27.2,-14.6) AB1(0,-15.4) AB3(0.8,-15.4) AB5(1.6,-15.4) AB6(2.4,-15.6) AB34(25.2,-15.6) AB35(26,-15.4) AB37(26.8,-15.4) AB39(27.6,-15.4) AC2(0.4,-16.2) AC4(1.2,-16.2) AC6(2.4,-16.4) AC34(25.2,-16.4) AC36(26.4,-16.2) AC38(27.2,-16.2) AD1(0,-17) AD3(0.8,-17) AD5(1.6,-17) AD6(2.4,-17.2) AD34(25.2,-17.2) AD35(26,-17) AD37(26.8,-17) AD39(27.6,-17) AE2(0.4,-17.8) AE4(1.2,-17.8) AE6(2.4,-18) AE34(25.2,-18) AE36(26.4,-17.8) AE38(27.2,-17.8) AF1(0,-18.6) AF3(0.8,-18.6) AF5(1.6,-18.6) AF6(2.4,-18.8) AF34(25.2,-18.8) AF35(26,-18.6) AF37(26.8,-18.6) AF39(27.6,-18.6) AG2(0.4,-19.4) AG4(1.2,-19.4) AG6(2.4,-19.6) AG34(25.2,-19.6) AG36(26.4,-19.4) AG38(27.2,-19.4) AH1(0,-20.2) AH3(0.8,-20.2) AH5(1.6,-20.2) AH6(2.4,-20.4) AH34(25.2,-20.4) AH35(26,-20.2) AH37(26.8,-20.2) AH39(27.6,-20.2) AJ2(0.4,-21) AJ4(1.2,-21) AJ6(2.4,-21.2) AJ34(25.2,-21.2) AJ36(26.4,-21) AJ38(27.2,-21) AK1(0,-21.8) AK3(0.8,-21.8) AK5(1.6,-21.8) AK6(2.4,-22) AK34(25.2,-22) AK35(26,-21.8) AK37(26.8,-21.8) AK39(27.6,-21.8) AL2(0.4,-22.6) AL4(1.2,-22.6) AL6(2.4,-22.8) AL34(25.2,-22.8) AL36(26.4,-22.6) AL38(27.2,-22.6) AM1(0,-23.4) AM3(0.8,-23.4) AM5(1.6,-23.4) AM6(2.4,-23.6) AM34(25.2,-23.6) AM35(26,-23.4) AM37(26.8,-23.4) AM39(27.6,-23.4) AP8(4,-25.2) AP9(4.8,-25.2) AP10(5.6,-25.2) AP11(6.4,-25.2) AP12(7.2,-25.2) AP13(8,-25.2) AP14(8.8,-25.2) AP15(9.6,-25.2) AP16(10.4,-25.2) AP17(11.2,-25.2) AP18(12,-25.2) AP19(12.8,-25.2) AP20(13.8,-25.2) AP21(14.8,-25.2) AP22(15.6,-25.2) AP23(16.4,-25.2) AP24(17.2,-25.2) AP25(18,-25.2) AP26(18.8,-25.2) AP27(19.6,-25.2) AP28(20.4,-25.2) AP29(21.2,-25.2) AP30(22,-25.2) AP31(22.8,-25.2) AP32(23.6,-25.2) AR8(4.2,-26) AR10(5.8,-26) AR12(7.4,-26) AR14(9,-26) AR16(10.6,-26) AR18(12.2,-26) AR20(13.8,-26) AR22(15.4,-26) AR24(17,-26) AR26(18.6,-26) AR28(20.2,-26) AR30(21.8,-26) AR32(23.4,-26) AT9(5,-26.4) AT11(6.6,-26.4) AT13(8.2,-26.4) AT15(9.8,-26.4) AT17(11.4,-26.4) AT19(13,-26.4) AT21(14.6,-26.4) AT23(16.2,-26.4) AT25(17.8,-26.4) AT27(19.4,-26.4) AT29(21,-26.4) AT31(22.6,-26.4) AU8(4.2,-26.8) AU10(5.8,-26.8) AU12(7.4,-26.8) AU14(9,-26.8) AU16(10.6,-26.8) AU18(12.2,-26.8) AU20(13.8,-26.8) AU22(15.4,-26.8) AU24(17,-26.8) AU26(18.6,-26.8) AU28(20.2,-26.8) AU30(21.8,-26.8) AU32(23.4,-26.8) AV9(5,-27.2) AV11(6.6,-27.2) AV13(8.2,-27.2) AV15(9.8,-27.2) AV17(11.4,-27.2) AV19(13,-27.2) AV21(14.6,-27.2) AV23(16.2,-27.2) AV25(17.8,-27.2) AV27(19.4,-27.2) AV29(21,-27.2) AV31(22.6,-27.2) AW8(4.2,-27.6) AW10(5.8,-27.6) AW12(7.4,-27.6) AW14(9,-27.6) AW16(10.6,-27.6) AW18(12.2,-27.6) AW20(13.8,-27.6) AW22(15.4,-27.6) AW24(17,-27.6) AW26(18.6,-27.6) AW28(20.2,-27.6) AW30(21.8,-27.6) AW32(23.4,-27.6) B9(5,-0.4) B11(6.6,-0.4) B13(8.2,-0.4) B15(9.8,-0.4) B17(11.4,-0.4) B19(13,-0.4) B21(14.6,-0.4) B23(16.2,-0.4) B25(17.8,-0.4) B27(19.4,-0.4) B29(21,-0.4) B31(22.6,-0.4) C8(4.2,-0.8) C10(5.8,-0.8) C12(7.4,-0.8) C14(9,-0.8) C16(10.6,-0.8) C18(12.2,-0.8) C20(13.8,-0.8) C22(15.4,-0.8) C24(17,-0.8) C26(18.6,-0.8) C28(20.2,-0.8) C30(21.8,-0.8) C32(23.4,-0.8) D9(5,-1.2) D11(6.6,-1.2) D13(8.2,-1.2) D15(9.8,-1.2) D17(11.4,-1.2) D19(13,-1.2) D21(14.6,-1.2) D23(16.2,-1.2) D25(17.8,-1.2) D27(19.4,-1.2) D29(21,-1.2) D31(22.6,-1.2) E8(4.2,-1.6) E10(5.8,-1.6) E12(7.4,-1.6) E14(9,-1.6) E16(10.6,-1.6) E18(12.2,-1.6) E20(13.8,-1.6) E22(15.4,-1.6) E24(17,-1.6) E26(18.6,-1.6) E28(20.2,-1.6) E30(21.8,-1.6) E32(23.4,-1.6) F8(4,-2.4) F9(4.8,-2.4) F10(5.6,-2.4) F11(6.4,-2.4) F12(7.2,-2.4) F13(8,-2.4) F14(8.8,-2.4) F15(9.6,-2.4) F16(10.4,-2.4) F17(11.2,-2.4) F18(12,-2.4) F19(12.8,-2.4) F20(13.8,-2.4) F21(14.8,-2.4) F22(15.6,-2.4) F23(16.4,-2.4) F24(17.2,-2.4) F25(18,-2.4) F26(18.8,-2.4) F27(19.6,-2.4) F28(20.4,-2.4) F29(21.2,-2.4) F30(22,-2.4) F31(22.8,-2.4) F32(23.6,-2.4) H1(0,-4.2) H3(0.8,-4.2) H5(1.6,-4.2) H6(2.4,-4) H34(25.2,-4) H35(26,-4.2) H37(26.8,-4.2) H39(27.6,-4.2) J2(0.4,-5) J4(1.2,-5) J6(2.4,-4.8) J34(25.2,-4.8) J36(26.4,-5) J38(27.2,-5) K1(0,-5.8) K3(0.8,-5.8) K5(1.6,-5.8) K6(2.4,-5.6) K34(25.2,-5.6) K35(26,-5.8) K37(26.8,-5.8) K39(27.6,-5.8) L2(0.4,-6.6) L4(1.2,-6.6) L6(2.4,-6.4) L34(25.2,-6.4) L36(26.4,-6.6) L38(27.2,-6.6) M1(0,-7.4) M3(0.8,-7.4) M5(1.6,-7.4) M6(2.4,-7.2) M34(25.2,-7.2) M35(26,-7.4) M37(26.8,-7.4) M39(27.6,-7.4) N2(0.4,-8.2) N4(1.2,-8.2) N6(2.4,-8) N34(25.2,-8) N36(26.4,-8.2) N38(27.2,-8.2) P1(0,-9) P3(0.8,-9) P5(1.6,-9) P6(2.4,-8.8) P34(25.2,-8.8) P35(26,-9) P37(26.8,-9) P39(27.6,-9) R2(0.4,-9.8) R4(1.2,-9.8) R6(2.4,-9.6) R34(25.2,-9.6) R36(26.4,-9.8) R38(27.2,-9.8) T1(0,-10.6) T3(0.8,-10.6) T5(1.6,-10.6) T6(2.4,-10.4) T34(25.2,-10.4) T35(26,-10.6) T37(26.8,-10.6) T39(27.6,-10.6) U2(0.4,-11.4) U4(1.2,-11.4) U6(2.4,-11.2) U34(25.2,-11.2) U36(26.4,-11.4) U38(27.2,-11.4) V1(0,-12.2) V3(0.8,-12.2) V5(1.6,-12.2) V6(2.4,-12) V34(25.2,-12) V35(26,-12.2) V37(26.8,-12.2) V39(27.6,-12.2) W2(0.4,-13) W4(1.2,-13) W6(2.4,-12.8) W34(25.2,-12.8) W36(26.4,-13) W38(27.2,-13) Y1(0,-13.8) Y3(0.8,-13.8) Y5(1.6,-13.8) Y6(2.4,-13.8) Y34(25.2,-13.8) Y35(26,-13.8) Y37(26.8,-13.8) Y39(27.6,-13.8)
  round 0.508 smd: AA9(4.8,-15) AA10(5.6,-15) AA11(6.4,-14.4) AA12(7.4,-14.4) AA13(8.4,-14.4) AA15(9.4,-14.4) AA16(10.4,-14.4) AA17(11.4,-14.4) AA18(12.4,-14.4) AA20(13.4,-14.4) AA21(14.4,-14.4) AA22(15.4,-14.4) AA23(16.4,-14.4) AA24(17.4,-14.4) AA26(18.4,-14.4) AA27(19.4,-14.4) AA28(20.4,-14.4) AA29(21.2,-15) AA30(22,-15) AA31(22.8,-15) AB11(6.4,-15.4) AB12(7.4,-15.4) AB13(8.4,-15.4) AB15(9.4,-15.4) AB16(10.4,-15.4) AB17(11.4,-15.4) AB18(12.4,-15.4) AB20(13.4,-15.4) AB21(14.4,-15.4) AB22(15.4,-15.4) AB23(16.4,-15.4) AB24(17.4,-15.4) AB26(18.4,-15.4) AB27(19.4,-15.4) AB28(20.4,-15.4) AC10(5.6,-16.2) AC11(6.4,-16.4) AC12(7.4,-16.4) AC13(8.4,-16.4) AC15(9.4,-16.4) AC16(10.4,-16.4) AC17(11.4,-16.4) AC18(12.4,-16.4) AC20(13.4,-16.4) AC21(14.4,-16.4) AC22(15.4,-16.4) AC23(16.4,-16.4) AC24(17.4,-16.4) AC26(18.4,-16.4) AC27(19.4,-16.4) AC28(20.4,-16.4) AC29(21.2,-16.2) AC30(22,-16.2) AD11(6.4,-17.4) AD12(7.4,-17.4) AD13(8.4,-17.4) AD15(9.4,-17.4) AD16(10.4,-17.4) AD17(11.4,-17.4) AD18(12.4,-17.4) AD20(13.4,-17.4) AD21(14.4,-17.4) AD22(15.4,-17.4) AD23(16.4,-17.4) AD24(17.4,-17.4) AD26(18.4,-17.4) AD27(19.4,-17.4) AD28(20.4,-17.4) AD29(21.2,-17.4) AF12(7.4,-18.4) AF13(8.4,-18.4) AF15(9.4,-18.4) AF16(10.4,-18.4) AF17(11.4,-18.4) AF18(12.4,-18.4) AF20(13.4,-18.4) AF21(14.4,-18.4) AF22(15.4,-18.4) AF23(16.4,-18.4) AF24(17.4,-18.4) AF26(18.4,-18.4) AF27(19.4,-18.4) AF28(20.4,-18.4) AG13(8.4,-19.4) AG15(9.4,-19.4) AG16(10.4,-19.4) AG17(11.4,-19.4) AG18(12.4,-19.4) AG20(13.4,-19.4) AG21(14.4,-19.4) AG22(15.4,-19.4) AG23(16.4,-19.4) AG24(17.4,-19.4) AG26(18.4,-19.4) AG27(19.4,-19.4) AH13(8.4,-20.4) AH15(9.4,-20.4) AH16(10.4,-20.4) AH17(11.4,-20.4) AH18(12.4,-20.4) AH20(13.4,-20.4) AH21(14.4,-20.4) AH22(15.4,-20.4) AH23(16.4,-20.4) AH24(17.4,-20.4) AH26(18.4,-20.4) AH27(19.4,-20.4) AJ13(7.8,-21.2) AJ14(9,-21.2) AJ16(10.2,-21.2) AJ17(11.4,-21.2) AJ19(12.6,-21.2) AJ20(13.8,-21.2) AJ21(15,-21.2) AJ23(16.2,-21.2) AJ24(17.4,-21.2) AJ26(18.6,-21.2) AJ27(19.8,-21.2) AK17(11.4,-22) AK19(12.6,-22) AK20(13.8,-22) AK21(15,-22) AK23(16.2,-22) AL19(12.6,-22.8) AL20(13.8,-22.8) AL21(15,-22.8) AM20(13.8,-23.6) AN7(3.2,-24.4) AN33(24.4,-24.4) G7(3.2,-3.2) G33(24.4,-3.2) H20(13.8,-4) J19(12.6,-4.8) J20(13.8,-4.8) J21(15,-4.8) K17(11.4,-5.6) K19(12.6,-5.6) K20(13.8,-5.6) K21(15,-5.6) K23(16.2,-5.6) L13(8.4,-6.4) L15(9.4,-6.4) L16(10.4,-6.4) L17(11.4,-6.4) L18(12.4,-6.4) L20(13.4,-6.4) L21(14.4,-6.4) L22(15.4,-6.4) L23(16.4,-6.4) L24(17.4,-6.4) L26(18.4,-6.4) L27(19.4,-6.4) M13(8.4,-7.4) M15(9.4,-7.4) M16(10.4,-7.4) M17(11.4,-7.4) M18(12.4,-7.4) M20(13.4,-7.4) M21(14.4,-7.4) M22(15.4,-7.4) M23(16.4,-7.4) M24(17.4,-7.4) M26(18.4,-7.4) M27(19.4,-7.4) N13(8.4,-8.4) N15(9.4,-8.4) N16(10.4,-8.4) N17(11.4,-8.4) N18(12.4,-8.4) N20(13.4,-8.4) N21(14.4,-8.4) N22(15.4,-8.4) N23(16.4,-8.4) N24(17.4,-8.4) N26(18.4,-8.4) N27(19.4,-8.4) R12(7.4,-9.4) R13(8.4,-9.4) R15(9.4,-9.4) R16(10.4,-9.4) R17(11.4,-9.4) R18(12.4,-9.4) R20(13.4,-9.4) R21(14.4,-9.4) R22(15.4,-9.4) R23(16.4,-9.4) R24(17.4,-9.4) R26(18.4,-9.4) R27(19.4,-9.4) R28(20.4,-9.4) T11(6.4,-10.4) T12(7.4,-10.4) T13(8.4,-10.4) T15(9.4,-10.4) T16(10.4,-10.4) T17(11.4,-10.4) T18(12.4,-10.4) T20(13.4,-10.4) T21(14.4,-10.4) T22(15.4,-10.4) T23(16.4,-10.4) T24(17.4,-10.4) T26(18.4,-10.4) T27(19.4,-10.4) T28(20.4,-10.4) T29(21.2,-10.2) U10(5.6,-11.4) U11(6.4,-11.4) U12(7.4,-11.4) U13(8.4,-11.4) U15(9.4,-11.4) U16(10.4,-11.4) U17(11.4,-11.4) U18(12.4,-11.4) U20(13.4,-11.4) U21(14.4,-11.4) U22(15.4,-11.4) U23(16.4,-11.4) U24(17.4,-11.4) U26(18.4,-11.4) U27(19.4,-11.4) U28(20.4,-11.4) U29(21.2,-11.4) U30(22,-11.4) V11(6.4,-12.4) V12(7.4,-12.4) V13(8.4,-12.4) V15(9.4,-12.4) V16(10.4,-12.4) V17(11.4,-12.4) V18(12.4,-12.4) V20(13.4,-12.4) V21(14.4,-12.4) V22(15.4,-12.4) V23(16.4,-12.4) V24(17.4,-12.4) V26(18.4,-12.4) V27(19.4,-12.4) V28(20.4,-12.4) W9(4.8,-12.6) W10(5.6,-12.6) W29(21.2,-12.6) W30(22,-12.6) W31(22.8,-12.6) Y8(4,-13.8) Y9(4.8,-13.8) Y10(5.6,-13.8) Y11(6.4,-13.4) Y12(7.4,-13.4) Y13(8.4,-13.4) Y15(9.4,-13.4) Y16(10.4,-13.4) Y17(11.4,-13.4) Y18(12.4,-13.4) Y20(13.4,-13.4) Y21(14.4,-13.4) Y22(15.4,-13.4) Y23(16.4,-13.4) Y24(17.4,-13.4) Y26(18.4,-13.4) Y27(19.4,-13.4) Y28(20.4,-13.4) Y29(21.2,-13.8) Y30(22,-13.8) Y31(22.8,-13.8) Y32(23.6,-13.8)
